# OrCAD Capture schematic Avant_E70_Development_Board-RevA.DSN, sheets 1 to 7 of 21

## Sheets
1 Title Page: title: Title Page; rev: 1.0; note: 305-PD-23-0976
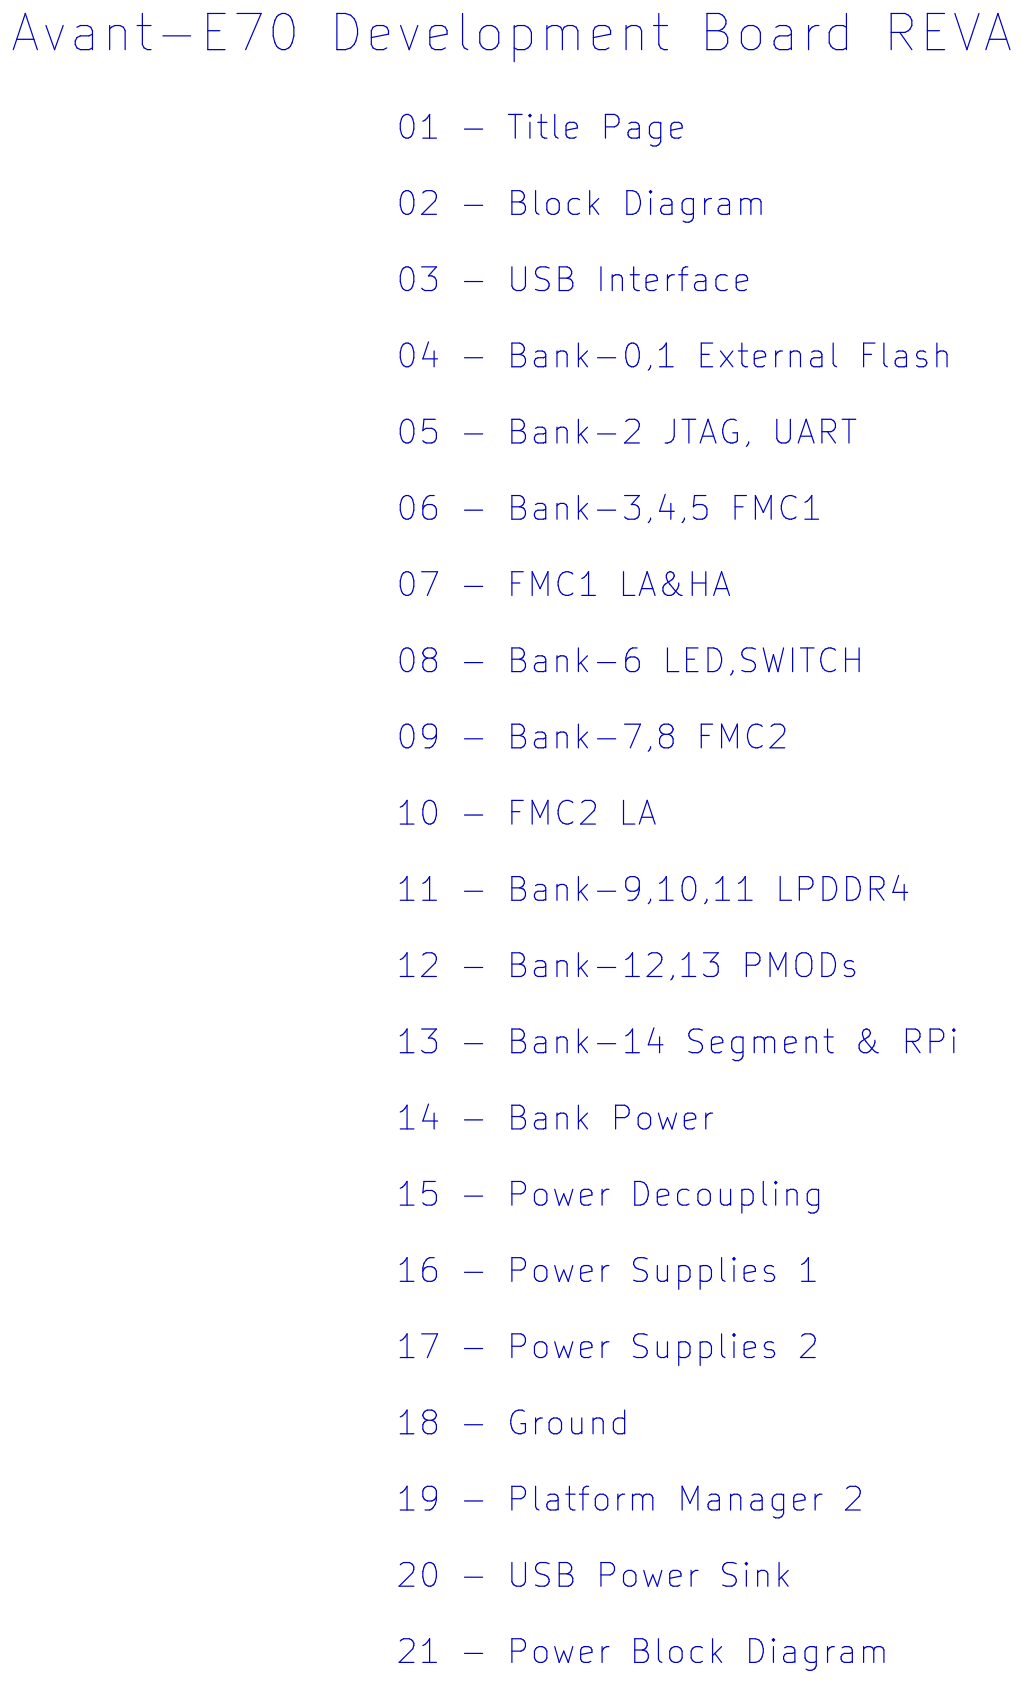
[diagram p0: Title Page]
2 Block Diagram: title: Block Diagram
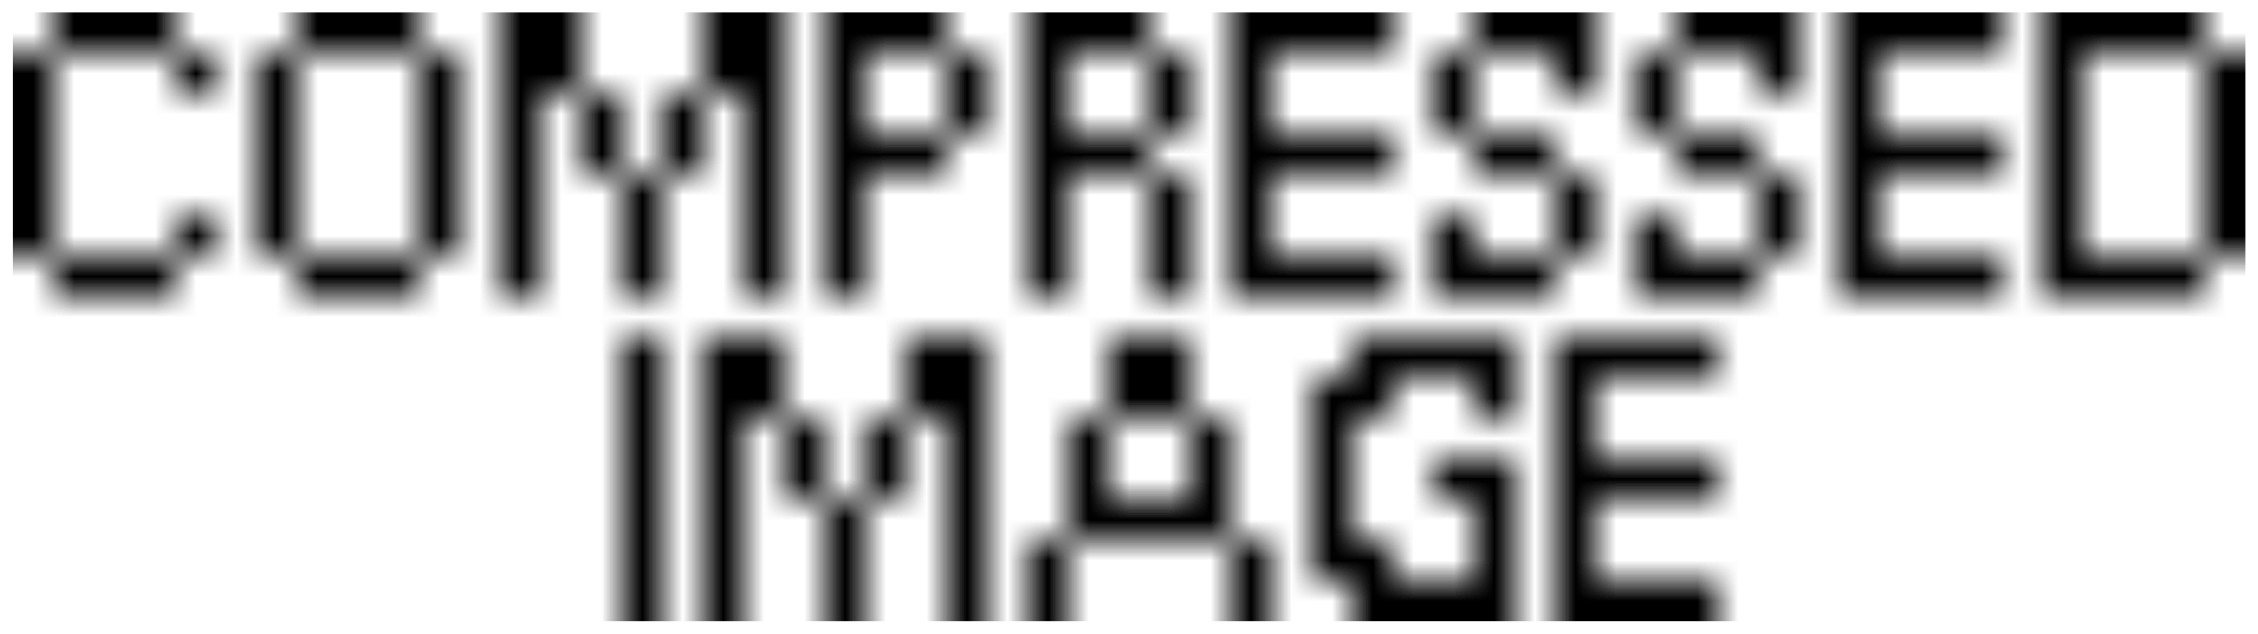
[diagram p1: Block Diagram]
3 USB Interface: size B; title: USB Interface
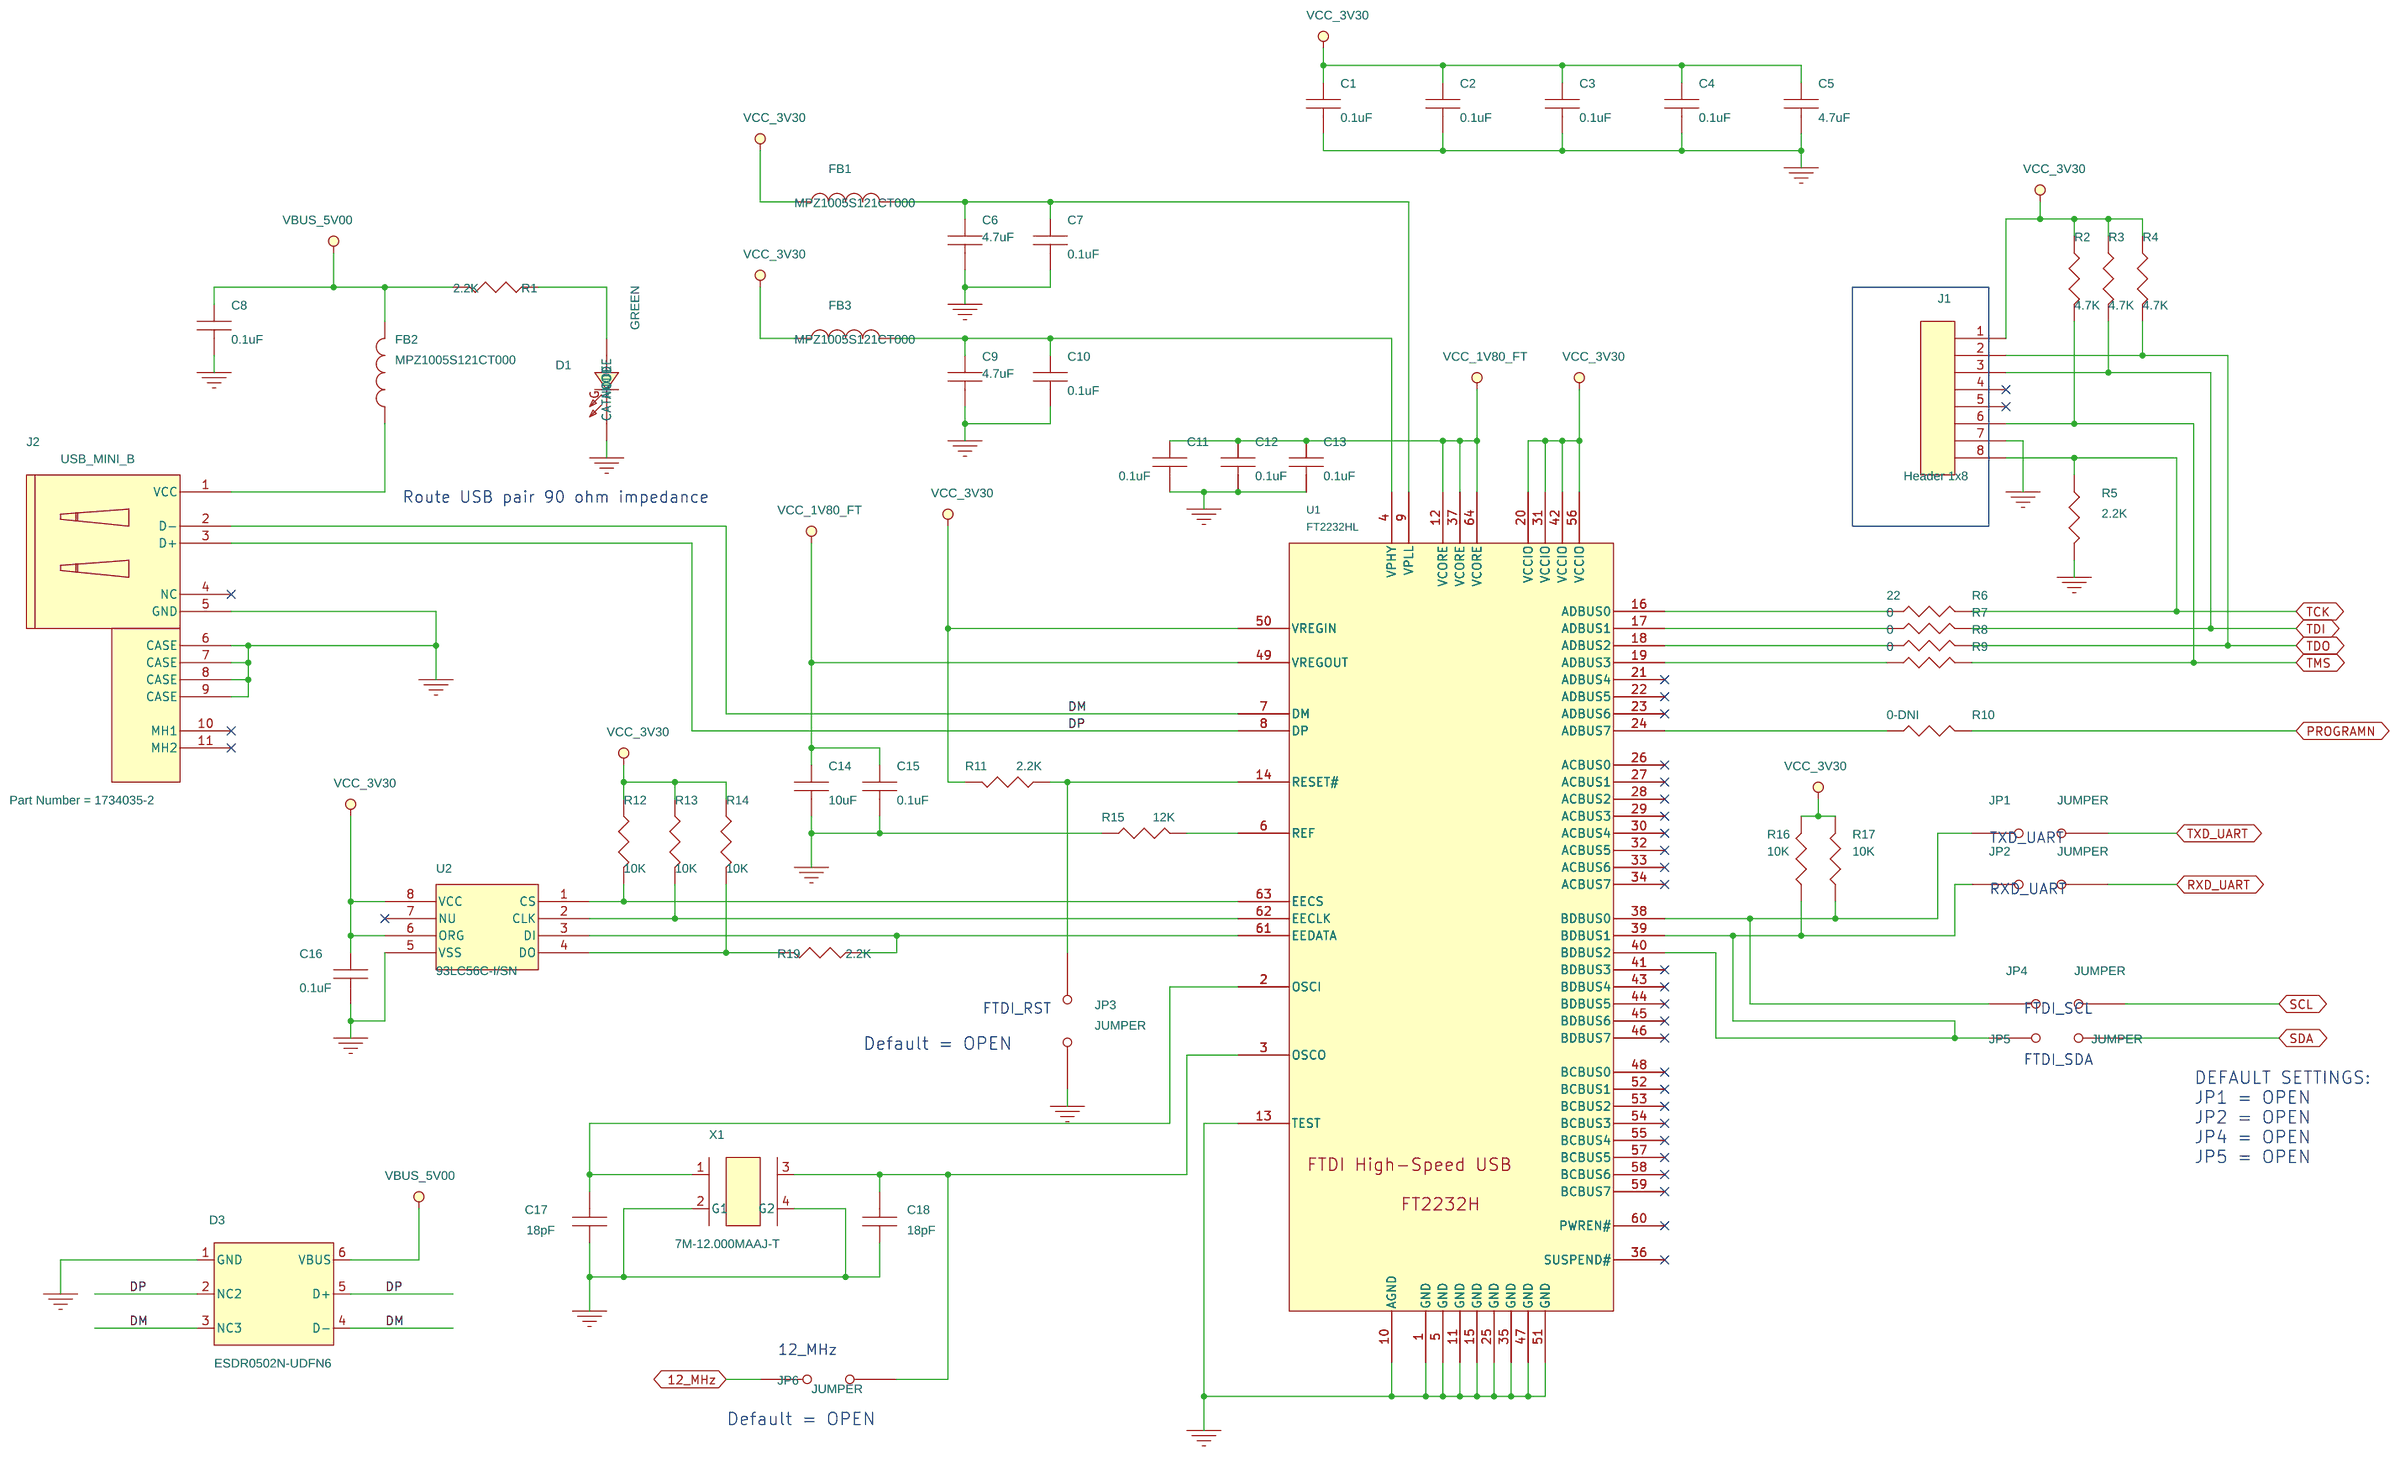
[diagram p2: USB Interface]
4 Bank-0,1 External Flash: size B; title: Bank-0,1 External Flash
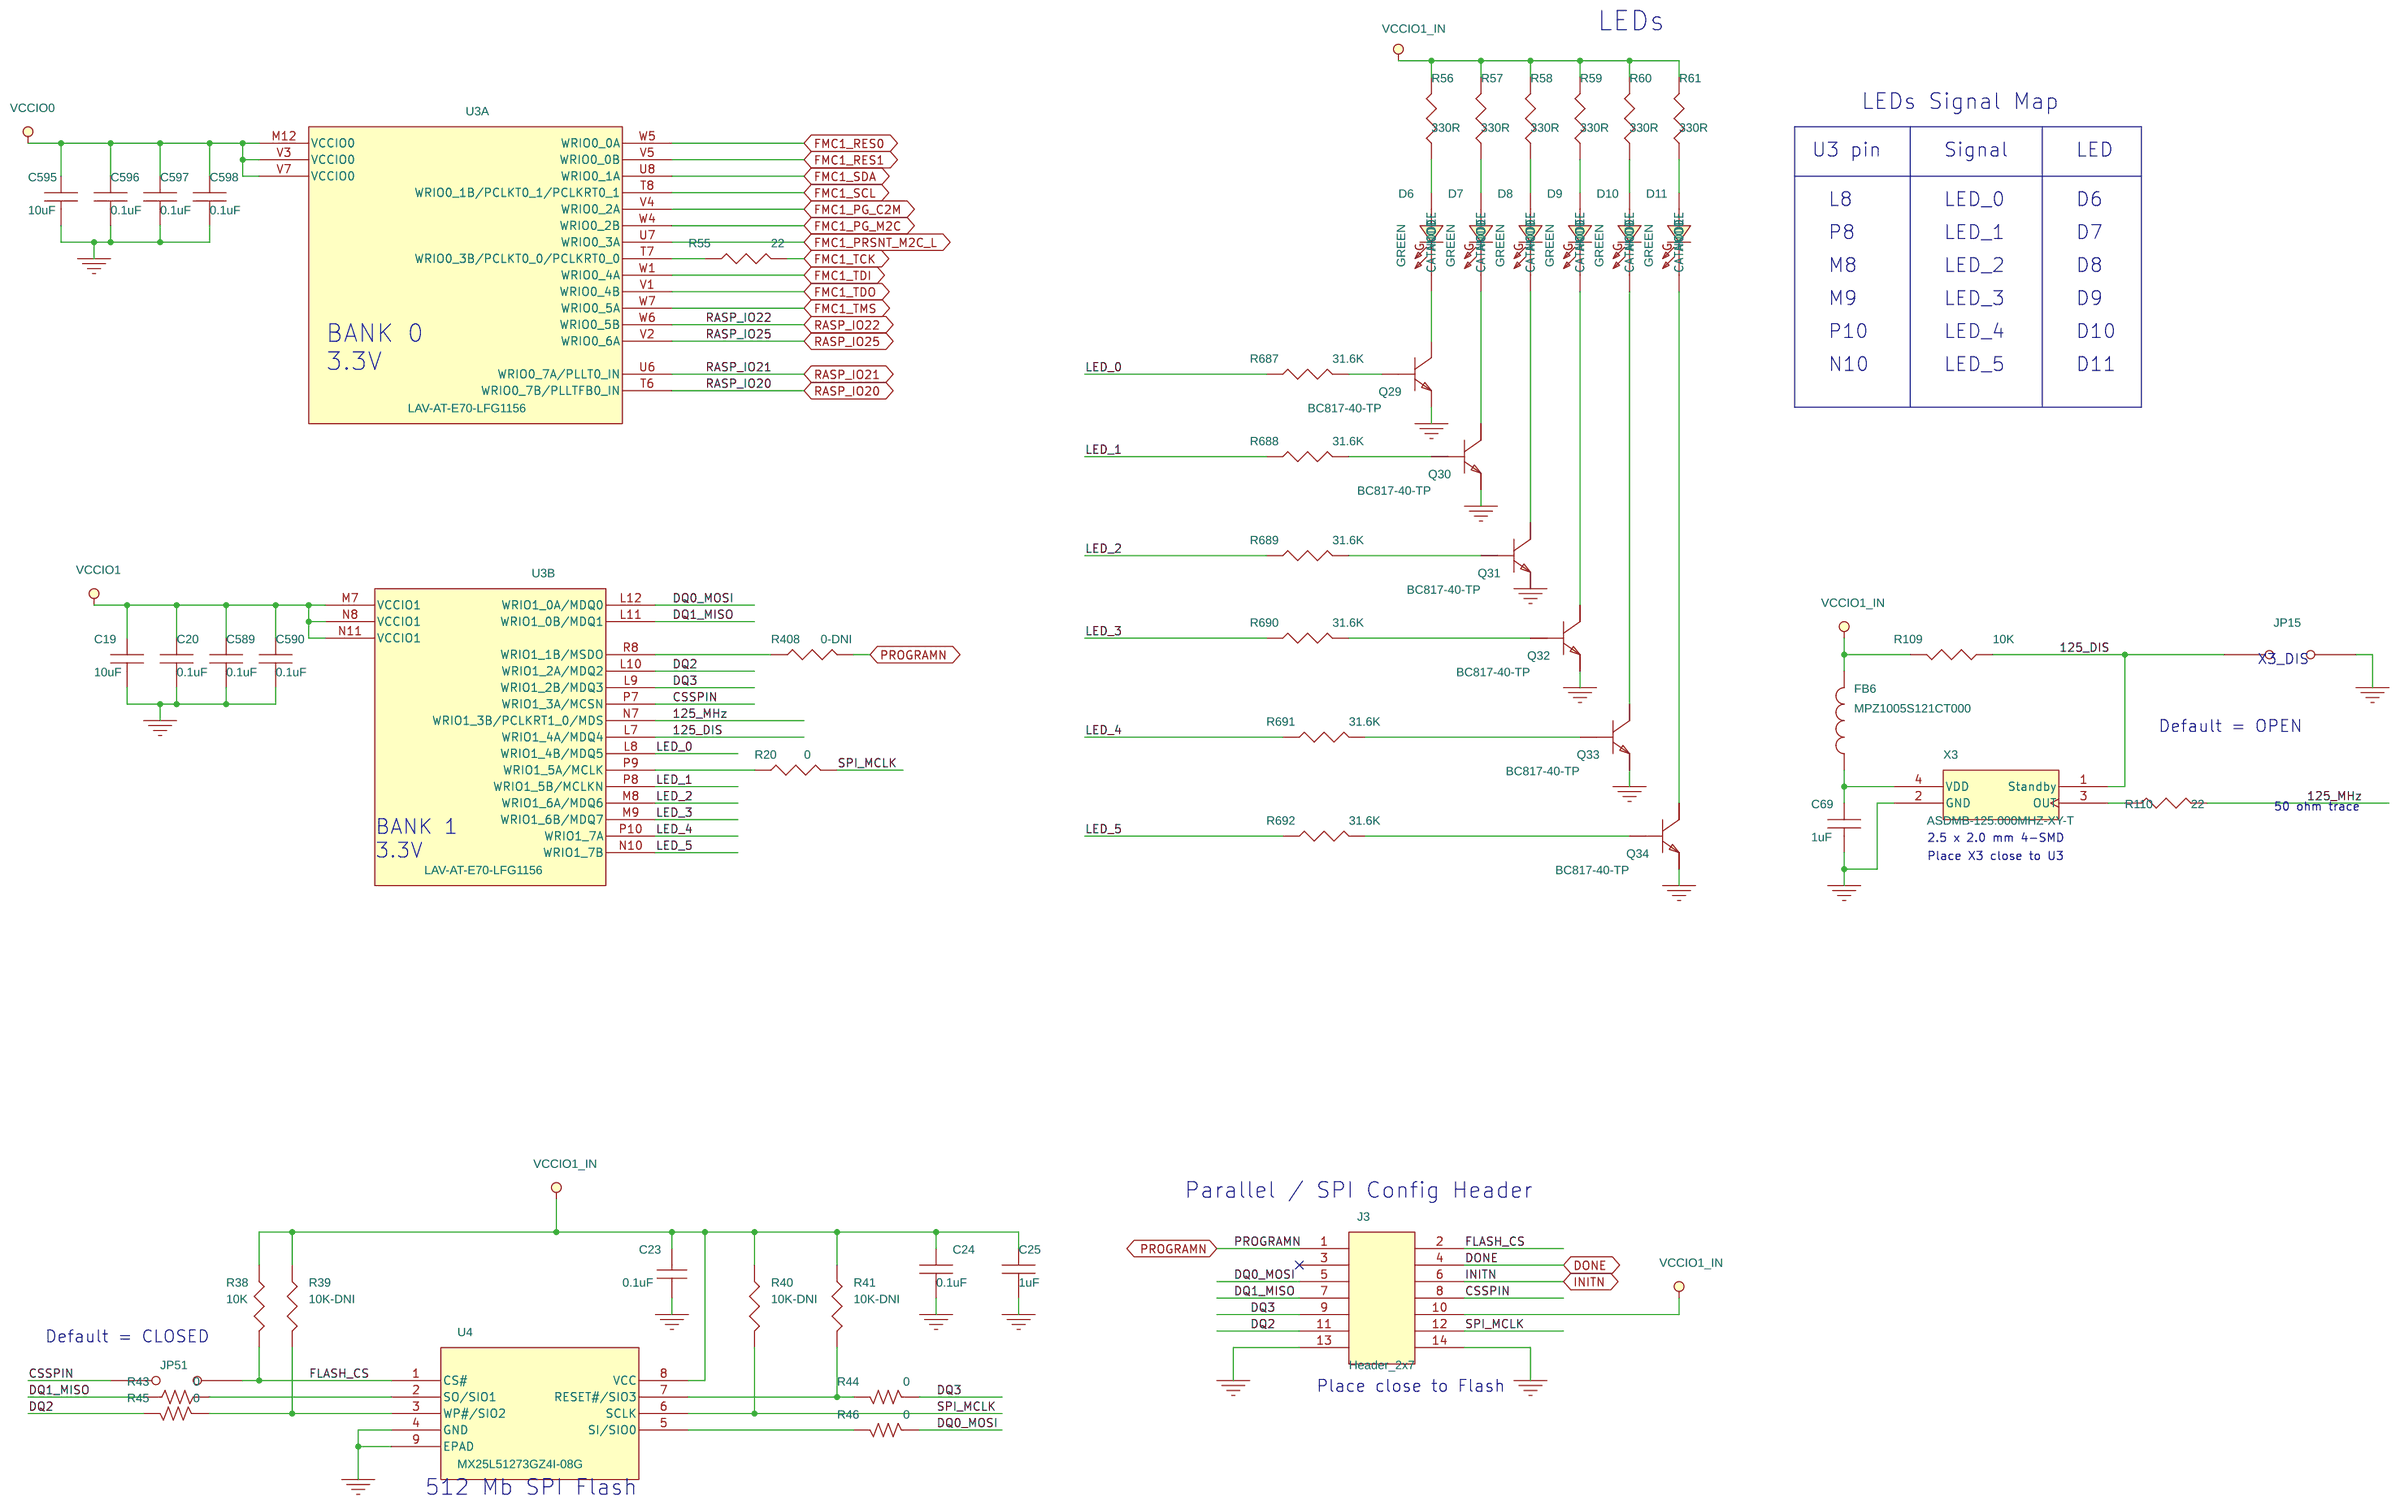
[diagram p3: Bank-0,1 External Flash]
5 Bank-2 JTAG, UART: size B; title: Bank-2 JTAG, UART
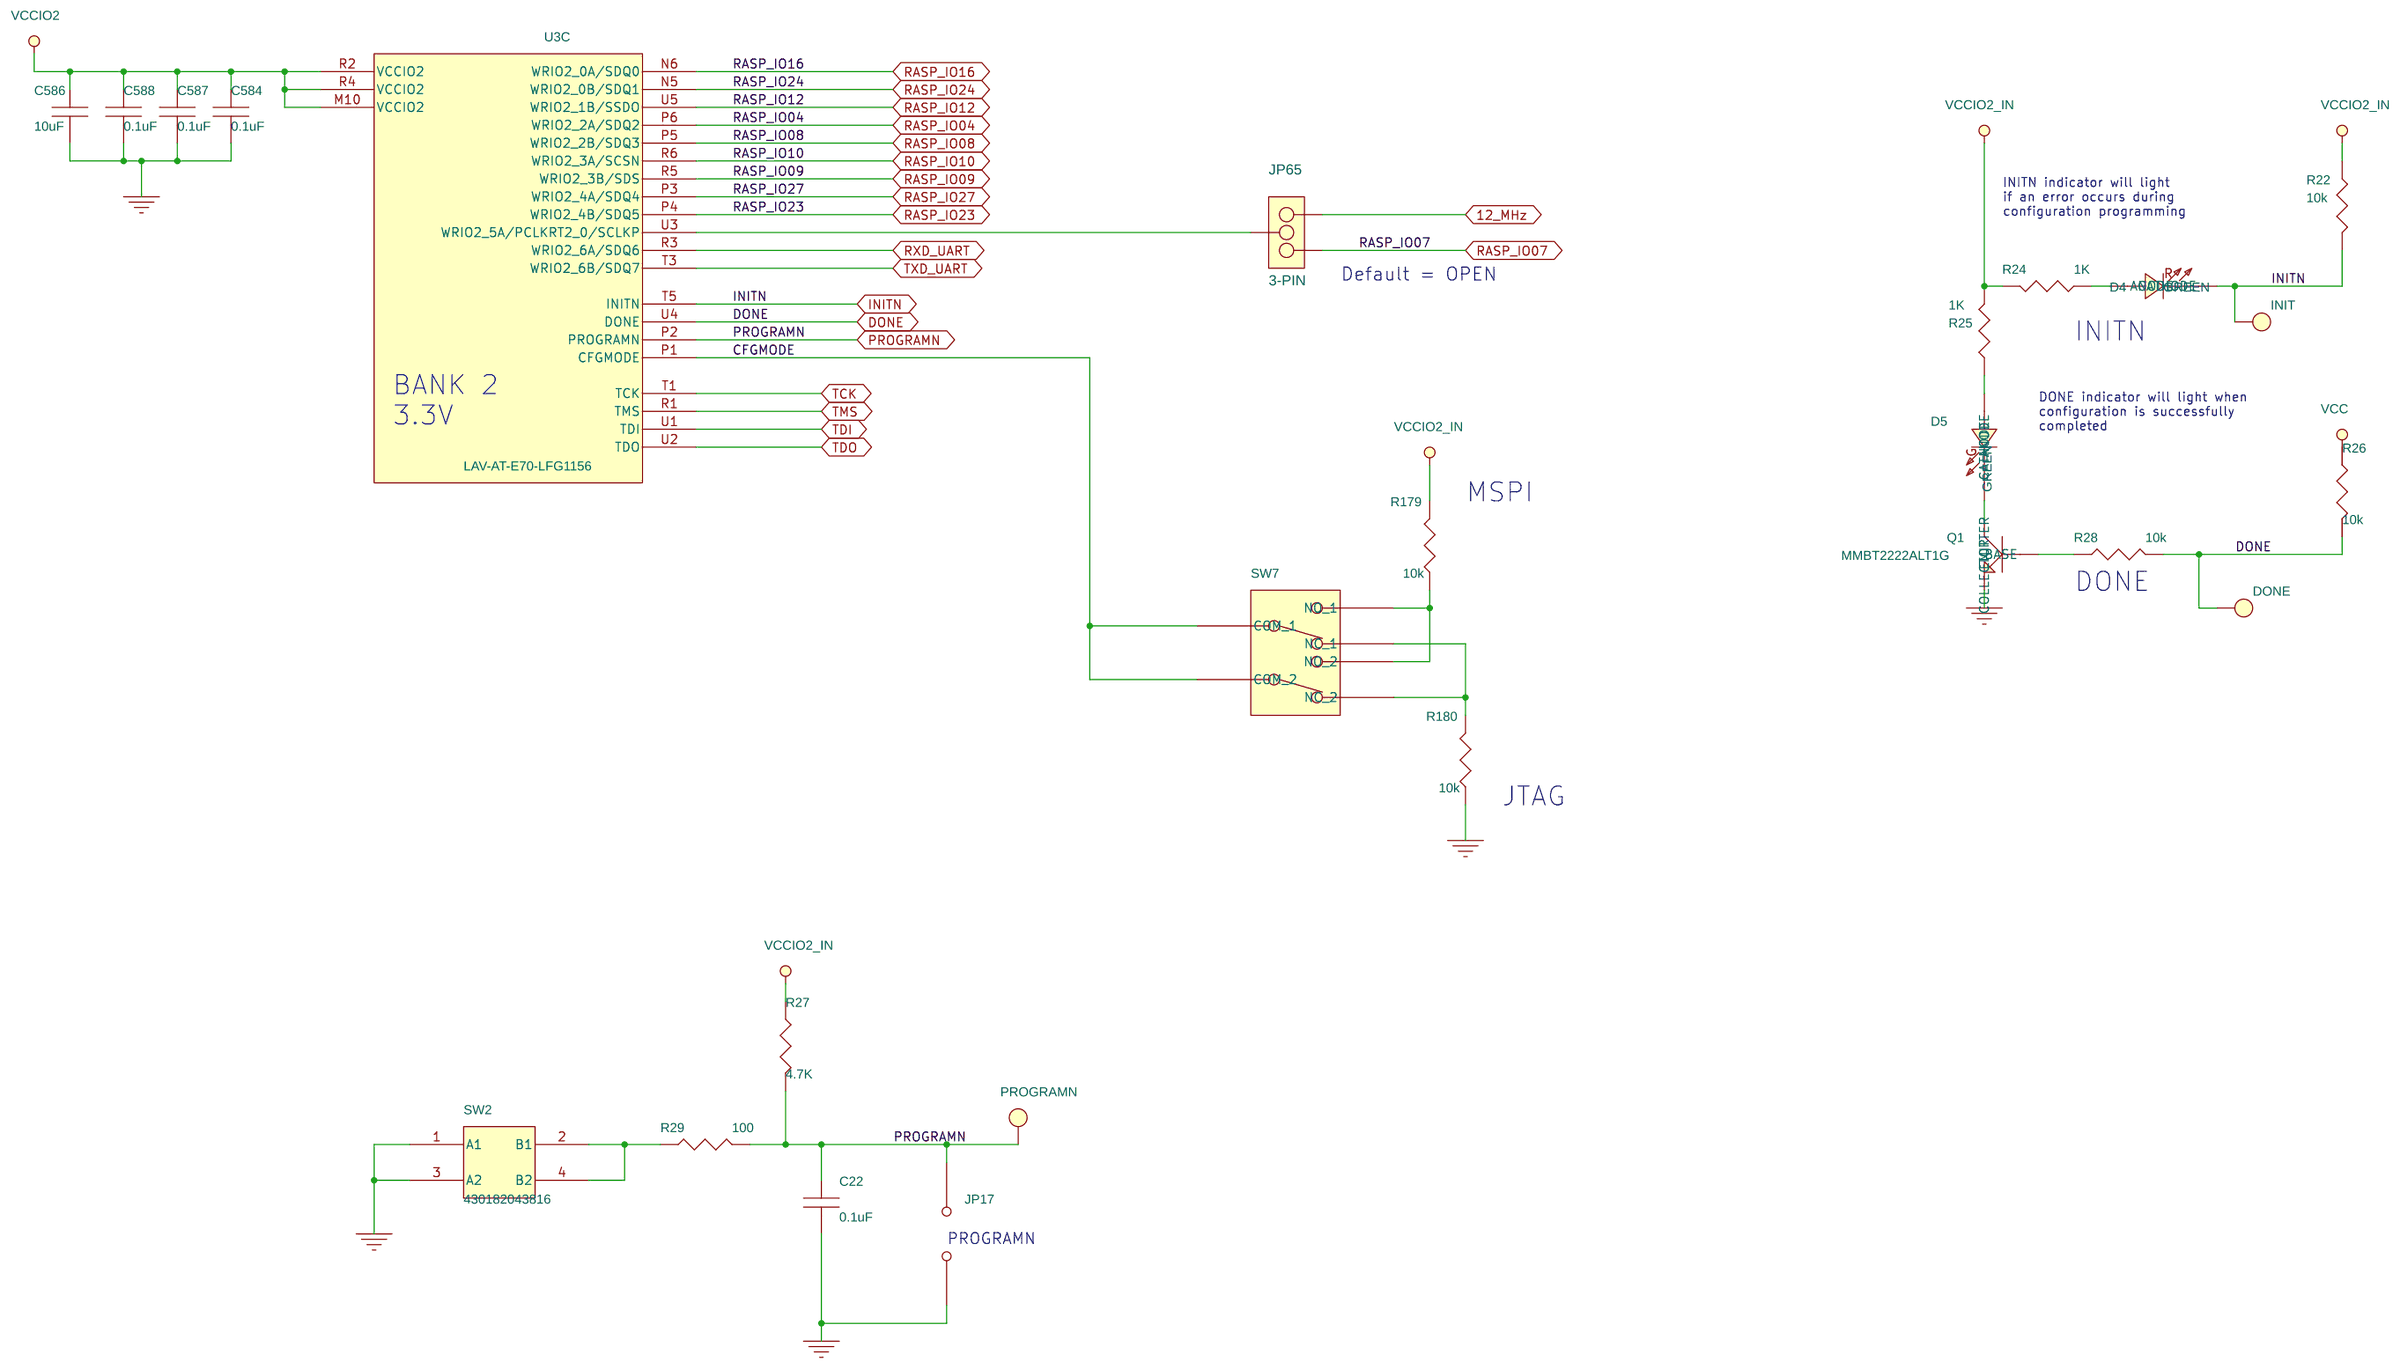
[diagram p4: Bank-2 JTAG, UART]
6 Bank-3,4,5 FMC1: size C; title: Bank-3,4,5 FMC1
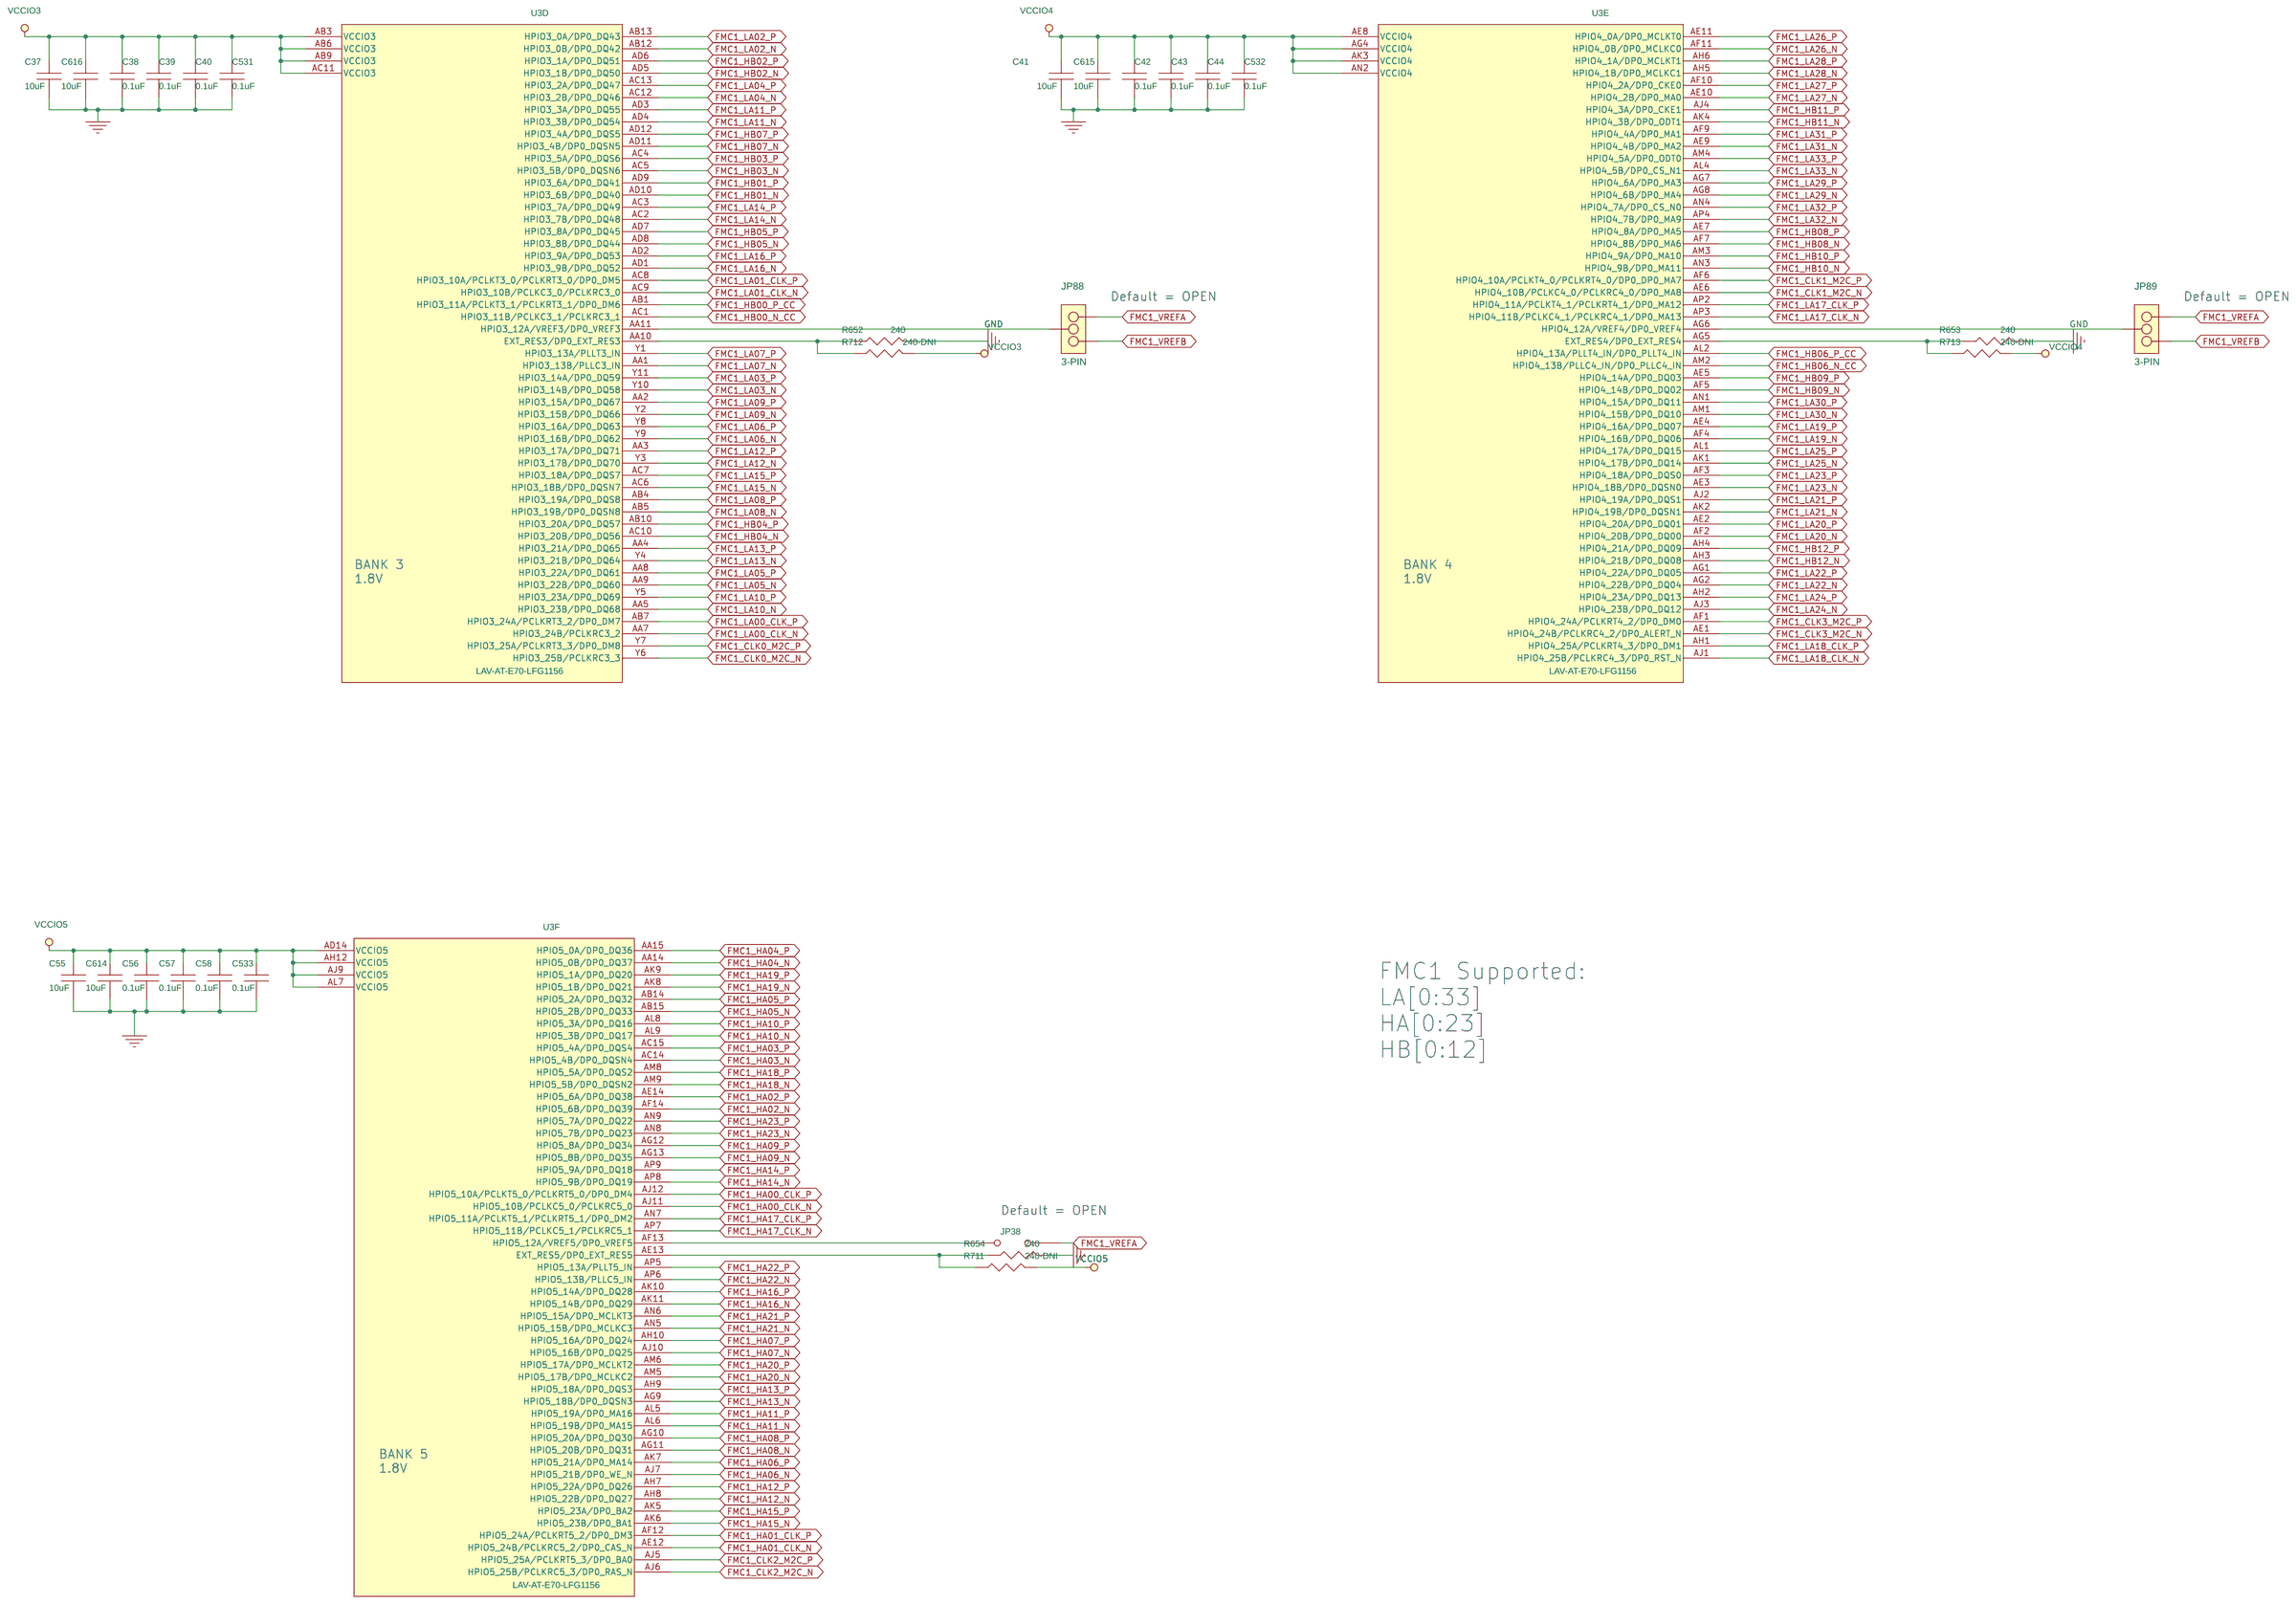
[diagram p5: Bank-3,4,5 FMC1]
7 FMC1 LA&HA: size C; title: FMC1 LA&HA
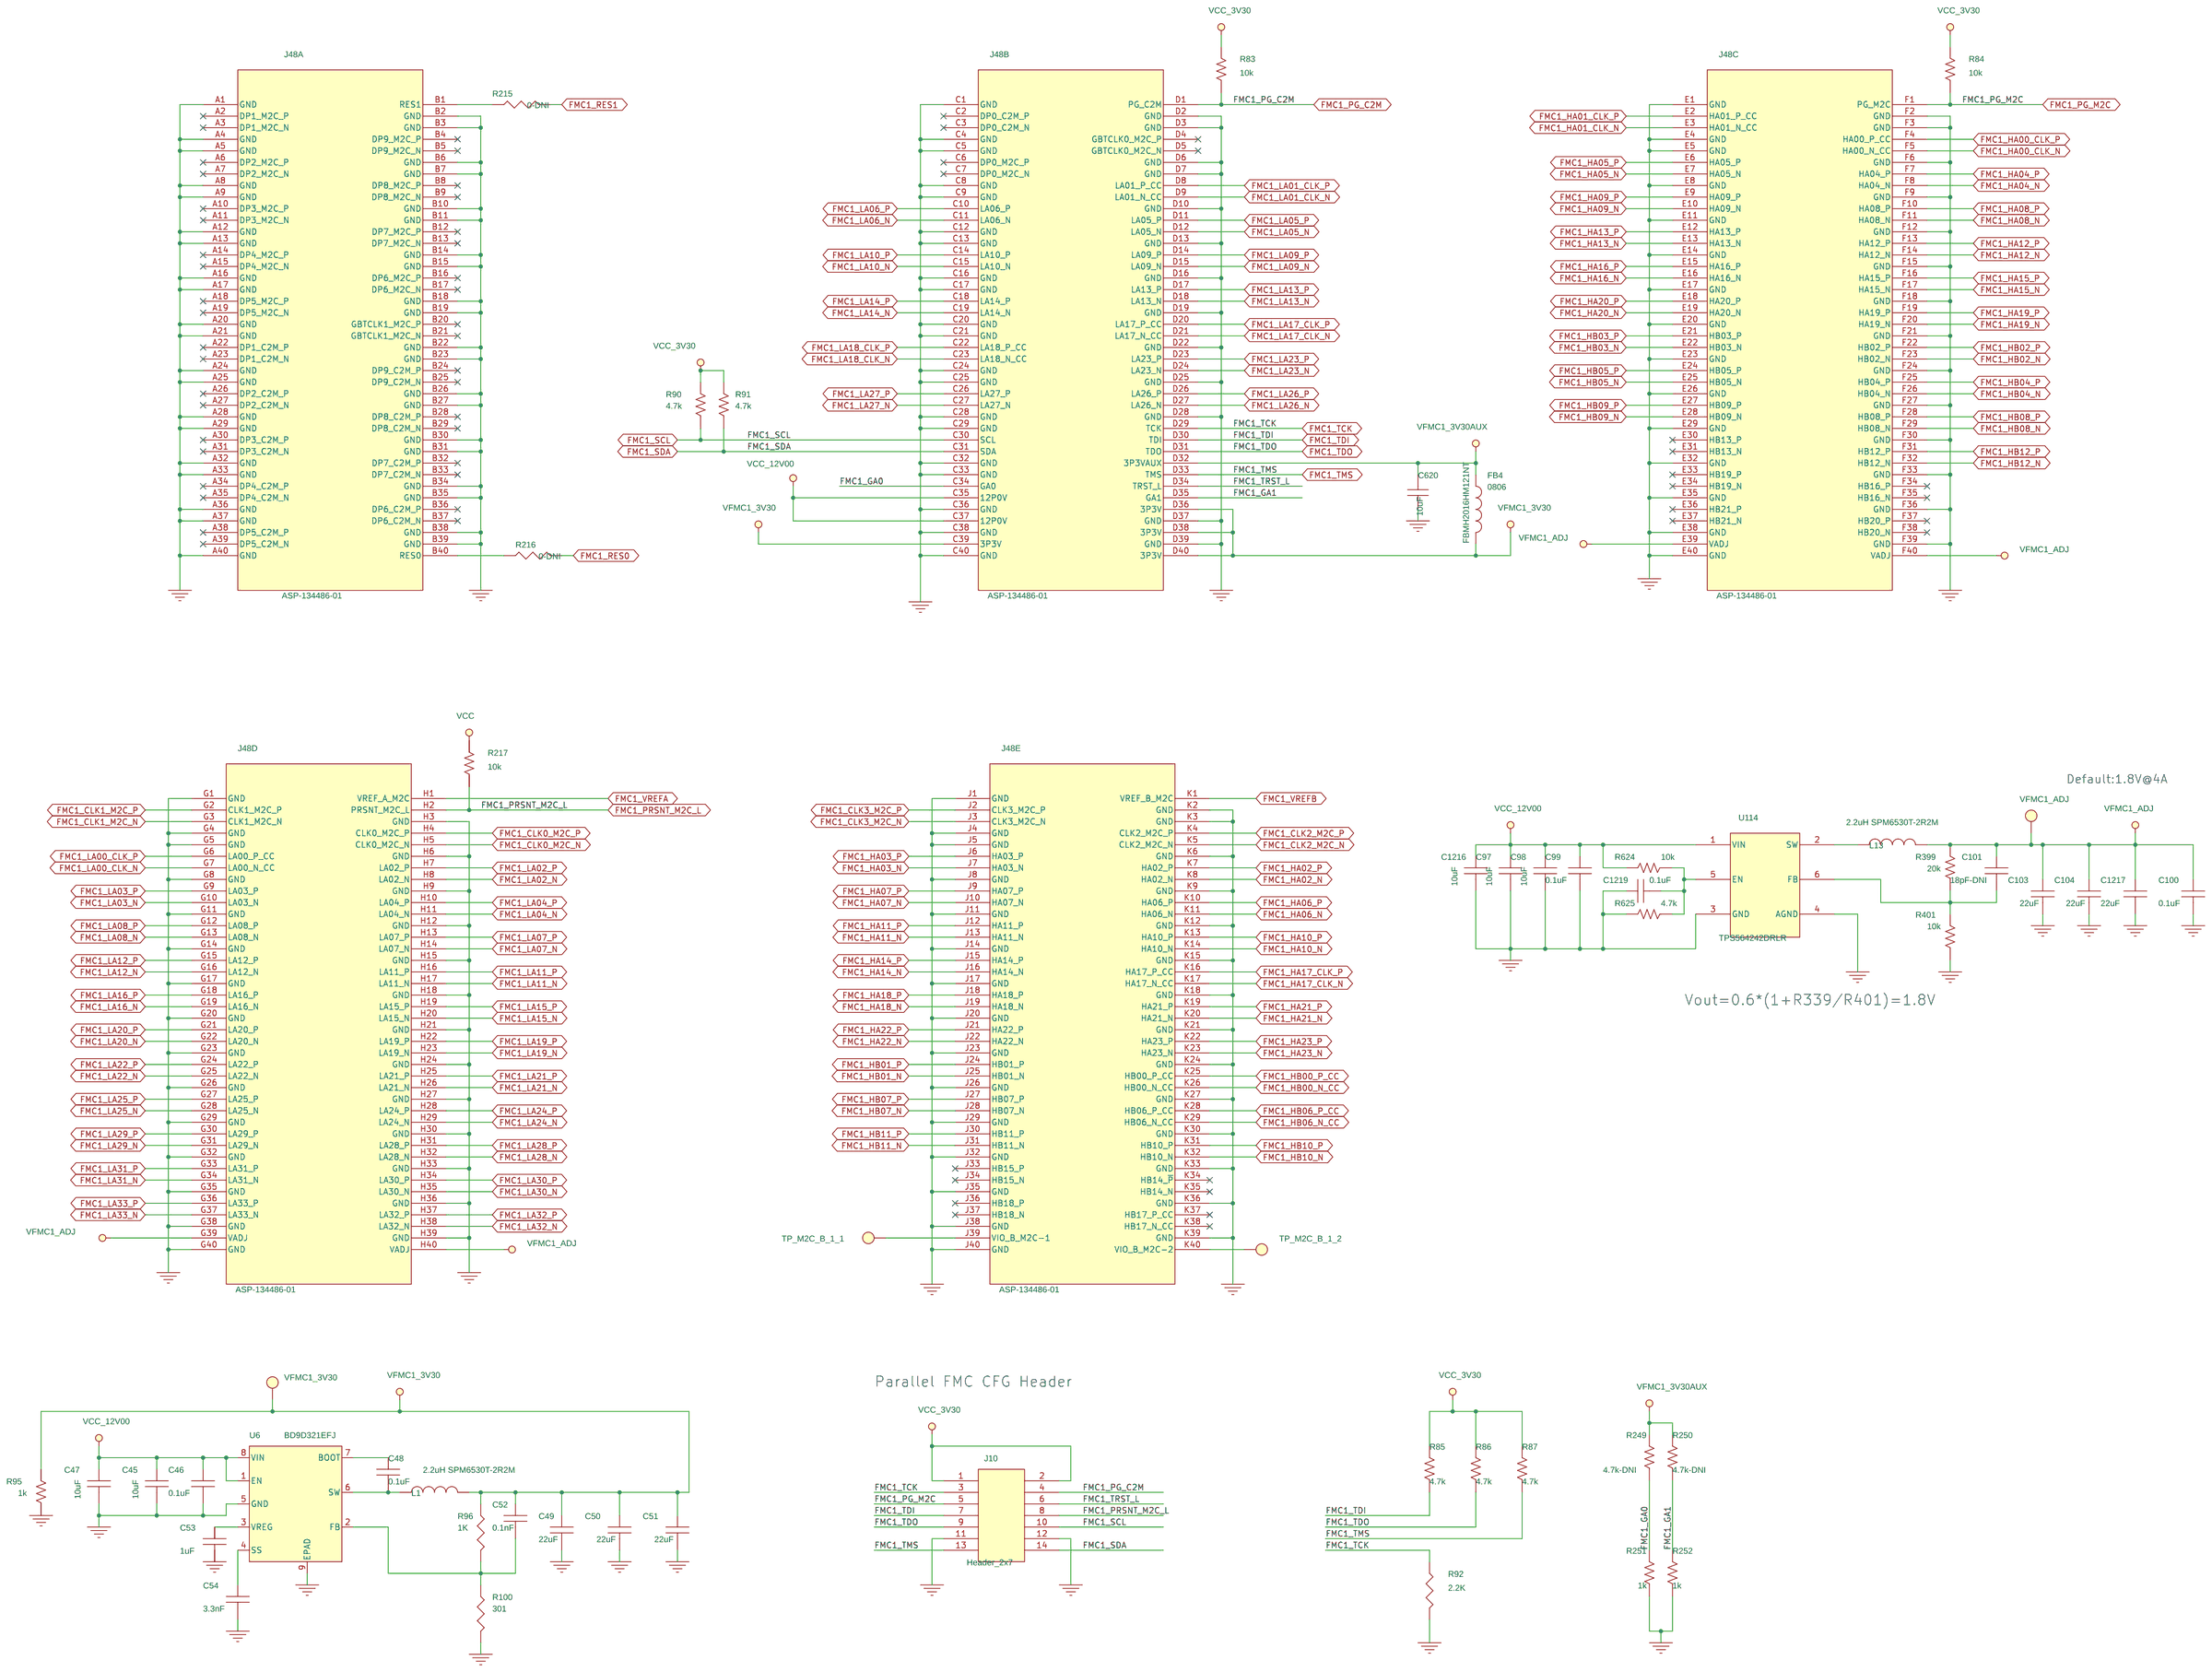
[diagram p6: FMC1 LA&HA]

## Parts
sheet Bank-0,1 External Flash
C19  10uF  [C0402]
C20  0.1uF  [C0201]
C23  0.1uF  [C0201]
C24  0.1uF  [C0201]
C25  1uF  [C0603]
C69  1uF  [C0603]
C589  0.1uF  [C0201]
C590  0.1uF  [C0201]
C595  10uF  [C0402]
C596  0.1uF  [C0201]
C597  0.1uF  [C0201]
C598  0.1uF  [C0201]
D6  GREEN  [APT1608]
D7  GREEN  [APT1608]
D8  GREEN  [APT1608]
D9  GREEN  [APT1608]
D10  GREEN  [APT1608]
D11  GREEN  [APT1608]
FB6  MPZ1005S121CT000  [FB0402]
J3  Header_2x7  [Header_2x7]
JP15  JUMPER  [Header_1x2]
JP51  J-2 Pin Jumper  [0p1_2-Pin_TH]
Q29  BC817-40-TP  [SOT23-3]
Q30  BC817-40-TP  [SOT23-3]
Q31  BC817-40-TP  [SOT23-3]
Q32  BC817-40-TP  [SOT23-3]
Q33  BC817-40-TP  [SOT23-3]
Q34  BC817-40-TP  [SOT23-3]
R20  0  [R0402]
R38  10K  [R0402]
R39  10K-DNI  [R0402]
R40  10K-DNI  [R0402]
R41  10K-DNI  [R0402]
R43  0  [R0402]
R44  0  [R0402]
R45  0  [R0402]
R46  0  [R0402]
R55  22  [R0402]
R56  330R  [R0603]
R57  330R  [R0603]
R58  330R  [R0603]
R59  330R  [R0603]
R60  330R  [R0603]
R61  330R  [R0603]
R109  10K  [R0603]
R110  22  [R0402]
R408  0-DNI  [R0402]
R687  31.6K  [R0603]
R688  31.6K  [R0603]
R689  31.6K  [R0603]
R690  31.6K  [R0603]
R691  31.6K  [R0603]
R692  31.6K  [R0603]
U4  MX25L51273GZ4I-08G  [8-WSON]
X3  ASDMB-125.000MHZ-XY-T  [x4-2520]
sheet Bank-2 JTAG, UART
C22  0.1uF  [C0201]
C584  0.1uF  [C0201]
C586  10uF  [C0402]
C587  0.1uF  [C0201]
C588  0.1uF  [C0201]
D4  GREEN  [APT1608]
D5  GREEN  [APT1608]
DONE  TestPoint  [TP50]
INIT  TestPoint  [TP50]
JP17  JUMPER  [Header_1x2]
JP65  3-PIN  [HDR254M-1X3]
PROGRAMN  TestPoint_SMT  [TPC32]
Q1  MMBT2222ALT1G  [MMBT2222ALT-1]
R22  10k  [R0603]
R24  1K  [R0603]
R25  1K  [R0603]
R26  10k  [R0603]
R27  4.7K  [R0603]
R28  10k  [R0603]
R29  100  [R0402]
R179  10k  [R0402]
R180  10k  [R0402]
SW2  430182043816  [430182043816]
SW7  SW-Wurth_452403012014  [452403012014]
sheet Bank-3,4,5 FMC1
C37  10uF  [C0402]
C38  0.1uF  [C0201]
C39  0.1uF  [C0201]
C40  0.1uF  [C0201]
C41  10uF  [C0402]
C42  0.1uF  [C0201]
C43  0.1uF  [C0201]
C44  0.1uF  [C0201]
C55  10uF  [C0402]
C56  0.1uF  [C0201]
C57  0.1uF  [C0201]
C58  0.1uF  [C0201]
C531  0.1uF  [C0201]
C532  0.1uF  [C0201]
C533  0.1uF  [C0201]
C614  10uF  [C0402]
C615  10uF  [C0402]
C616  10uF  [C0402]
JP38  J-2 Pin Jumper  [0p1_2-Pin_TH]
JP88  3-PIN  [HDR254M-1X3]
JP89  3-PIN  [HDR254M-1X3]
R652  240  [R0402]
R653  240  [R0402]
R654  240  [R0402]
R711  240-DNI  [R0402]
R712  240-DNI  [R0402]
R713  240-DNI  [R0402]
sheet Bank-12,13 PMODs
U3  LAV-AT-E70-LFG1156  [LAV-AT-500-L_1156]  (sections A,B,C,D,E,F,G,H,I,J,K,L,M,N,O,P,Q,R,S,T,U)
sheet FMC1 LA&HA
C45  10uF  [C0603]
C46  0.1uF  [C0201]
C47  10uF  [C0603]
C48  0.1uF  [C0201]
C49  22uF  [C0603]
C50  22uF  [C0603]
C51  22uF  [C0603]
C52  0.1nF  [C0603]
C53  1uF  [C0603]
C54  3.3nF  [C0201]
C97  10uF  [C0603]
C98  10uF  [C0603]
C99  0.1uF  [C0201]
C100  0.1uF  [C0201]
C101  18pF-DNI  [C0402]
C103  22uF  [C0603]
C104  22uF  [C0603]
C620  10uF  [C0402]
C1216  10uF  [C0603]
C1217  22uF  [C0603]
C1219  0.1uF  [C0201]
FB4  FBMH2016HM121NT  [0806]
J10  Header_2x7  [Header_2x7]
J48  ASP-134486-01  [ASP-134486-01]  (sections A,B,C,D,E)
L1  2.2uH SPM6530T-2R2M  [SPM6530T-2R2M]
L13  2.2uH SPM6530T-2R2M  [SPM6530T-2R2M]
R83  10k  [R0603]
R84  10k  [R0603]
R85  4.7k  [R0603]
R86  4.7k  [R0603]
R87  4.7k  [R0603]
R90  4.7k  [R0603]
R91  4.7k  [R0603]
R92  2.2K  [R0603]
R95  1k  [R0603]
R96  1K  [R0402]
R100  301  [R0402]
R215  0-DNI  [R0603]
R216  0-DNI  [R0603]
R217  10k  [R0603]
R249  4.7k-DNI  [R0603]
R250  4.7k-DNI  [R0603]
R251  1k  [R0603]
R252  1k  [R0603]
R399  20k  [R0603]
R401  10k  [R0603]
R624  10k  [R0603]
R625  4.7k  [R0603]
TP_M2C_B_1_1  TestPoint  [TP50]
TP_M2C_B_1_2  TestPoint  [TP50]
U6  BD9D321EFJ  [HTSOP_8_BD9D321]
U114  TPS564242DRLR  [SOT-563-6]
VFMC1_3V30  VTTVREF  [TP_50]
VFMC1_ADJ  TestPoint_SMT  [TPC32]
sheet USB Interface
C1  0.1uF  [C0201]
C2  0.1uF  [C0201]
C3  0.1uF  [C0201]
C4  0.1uF  [C0201]
C5  4.7uF  [C0603]
C6  4.7uF  [C0603]
C7  0.1uF  [C0201]
C8  0.1uF  [C0201]
C9  4.7uF  [C0603]
C10  0.1uF  [C0201]
C11  0.1uF  [C0201]
C12  0.1uF  [C0201]
C13  0.1uF  [C0201]
C14  10uF  [C0402]
C15  0.1uF  [C0201]
C16  0.1uF  [C0201]
C17  18pF  [C0402]
C18  18pF  [C0402]
D1  GREEN  [APT1608]
D3  ESDR0502N-UDFN6  [UDFN6_040]
FB1  MPZ1005S121CT000  [FB0402]
FB2  MPZ1005S121CT000  [FB0402]
FB3  MPZ1005S121CT000  [FB0402]
J1  Header 1x8  [hdr_amp_87220_8_1x8_100]
J2  USB_MINI_B  [USB_MINI_B-1734035-2]
JP1  JUMPER  [Header_1x2]
JP2  JUMPER  [Header_1x2]
JP3  JUMPER  [Header_1x2]
JP4  JUMPER  [Header_1x2]
JP5  JUMPER  [Header_1x2]
JP6  JUMPER  [Header_1x2]
R1  2.2K  [R0603]
R2  4.7K  [R0603]
R3  4.7K  [R0603]
R4  4.7K  [R0603]
R5  2.2K  [R0603]
R6  22  [R0402]
R7  0  [R0402]
R8  0  [R0402]
R9  0  [R0402]
R10  0-DNI  [R0402]
R11  2.2K  [R0603]
R12  10K  [R0603]
R13  10K  [R0603]
R14  10K  [R0603]
R15  12K  [R0603]
R16  10K  [R0603]
R17  10K  [R0603]
R19  2.2K  [R0603]
U1  FT2232HL  [tqfp64_0p5_12p2x12p2_h1p6]
U2  93LC56C-I/SN  [so8_50_244]
X1  7M-12.000MAAJ-T  [xtal_4p_7m]

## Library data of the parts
C19 C37 C41 C55 C586 C595 C614-C616 = 10uF_0603
C1-C5 C7 C8 C10-C13 C16 C20 C24 C25 C38-C40 C42-C44 C46 C48 C56-C58 C99 C100 C531-C533 C584 C587-C590 C596-C598 C1219 = 0u1_0402: CAP CER 0.1UF 25V 10% X5R 0201; Manufacturer: Murata; Manufacturer Part Number: GRM033R61E104KE14J
C23 C620 = CAP_NP: COMPFIXED: NO; COMPGROUP: 0; COMPHEIGHT: 0.000; COMPKEY: NO; COMPLOC: [1820.000,2015.000]; COMPLOCKED: NO; COMPROT: 270; COMPSIDE: TOP; DECOUPLER: NO; FPLIST: SM/C_0402; MEMORY: NO
C15 C22 C69 = 0u1_0402: CAP CER 0.1UF 16V 10% X7R 0402
D1 D5-D11 = LED-SMT1206_GREEN_3
FB1-FB3 FB6 = INDUCTOR_1: FERRITE BEAD 120 OHM 0402 1LN; Manufacturer: TDK Corporation
J3 J10 = Header_2x7
JP1-JP6 JP15 JP17 = JUMPER_0
JP38 JP51 = J-2_Pin_Jumper: Manufacturer Part Number: 22-28-4020
Q29-Q34 = TRANS_NPN_45V_0_0.8A_SOT-23: TRANS NPN 45V 0.8A SOT-23; Manufacturer: Micro Commercial Co
R20 R55 R408 = R_v2: RES SMD 33 OHM 1% 1/10W 0402; Manufacturer: Panasonic; Manufacturer Part Number: ERJ-2RKF33R0X
R38 = R0402_10K_5%_VISHAY: Manufacturer Part Number: CRCW040210K0JNED
R39-R41 = R0402_10K_NP: Manufacturer Part Number: ERJ-2GEJ103X
R43-R46 = R: RES SMD 0.0OHM JUMPER 1/10W 0402; COMPFIXED: NO; COMPHEIGHT: 0.000; COMPKEY: NO; COMPLOC: [3325.000,1400.000]; COMPLOCKED: NO; COMPROT: 180; COMPSIDE: TOP; DECOUPLER: NO; FPLIST: AX/RC05; MEMORY: NO; Manufacturer: Panasonic; Manufacturer Part Number: ERJ-2GE0R00X
R24 R25 R56-R61 = 1k_0402: RES 1K OHM 1/10W 1% 0603 SMD; Digikey P/N: 311-1.00KHRCT-ND; Manufacturer Part Number: RC0603FR-071KL
R109 = RESISTOR: RES 10K OHM 1/10W 5% 0603
R110 = 1R_0.25W_0603: Manufacturer: Vishay
R687-R692 = R_10K_0603: Manufacturer Part Number: RC1608F103CS
U4 = U-W25Q512JVEIM_512Mb_Flash_0
X3 = ASDMB: Assy: DNI
D4 = LED-SMT1206_RED_2
DONE INIT TP_M2C_B_1_1 TP_M2C_B_1_2 = T_POINT_R
JP65 JP88 JP89 = 3-PINS_0.1_SINGLE_LINE_PIN
PROGRAMN VFMC1_ADJ = T_POINT_R: Assy: DNI
Q1 = 2N2222_0
R22 R26 = R_v2: RES SMD 10K OHM 1% 1/16W 0402; MFG: Yageo; MFG P/N: RC0402FR-0710KL; Manufacturer: Yageo; Manufacturer Part Number: RC0402FR-0710KL
R2-R4 R27 = 5k1_0402: RES 4.70K OHM 1/10W 1% 0603 SMD; Digikey P/N: 541-4.70KHTR-ND; Manufacturer: Vishay; Manufacturer Part Number: CRCW06034K70FKEA
R28 = RES_0: RES SMD 10K OHM 1% 1/16W 0402; MFG: Yageo; MFG P/N: RC0402FR-0710KL; Manufacturer: Yageo; Manufacturer Part Number: RC0402FR-0710KL
R29 = RES_10K_1W16_0402_5P: RES SMD 100 OHM 1% 1/10W 0402; Digikey P/N: RMCF0603JT10K0TR-ND; MFG: Pansonic; MFG P/N: ERJ-2RKF1000X; Manufacturer: Pansonic; Manufacturer Part Number: ERJ-2RKF1000X; Wattage: 1/10W
R179 R180 = RES_10K_1W16_0402_5P: RES SMD 10K OHM 1% 1/16W 0402; Digikey P/N: 311-10.0KLRTR-ND; Manufacturer: Yageo; Manufacturer Part Number: RC0402FR-0710KL
SW2 = EVQP0_0: SWITCH TACTILE SPST-NO 0.05A 12V; Cost Ea/1k: $ 0.11025 (1000-4999), 0.09135 (5000+); Digikey P/N: CKN9112TR-ND; Distributor: Digi-Key; MFG: C&K Components; Manufacturer: C&K Components
SW7 = SW-Wurth_452403012014
R7-R9 R652-R654 R711-R713 = 0R_0603: RES 0.0 OHM 1/10W JUMP 0603 SMD
U3 = LAV-AT-E70-LFG1156_6
C45 C47 C97 C98 C1216 = 10uF_0603: CAP CER 10UF 25V X5R 1206; Manufacturer Part Number: TMK316BJ106KL-T
C49-C51 C103 C104 = 10uF_0603: CAP CER 22UF 10V X5R 0603; Manufacturer: Murata; Manufacturer Part Number: GRM188R61A226ME15D
C52 C101 = 10uF_0603: CAP CER 100PF 50V C0G/NPO 0603; Manufacturer: Yageo; Manufacturer Part Number: CC0603JRNPO9BN101
C53 C1217 = 10uF_0603: CAP CER 1UF 25V 10% X7R 0603; Manufacturer Part Number: TMK107B7105KA-T
C54 = 0u1_0402: CAP CER 3300PF 25V X7R 0201; Manufacturer: Murata; Manufacturer Part Number: GRM033R71E332KA12D
FB4 = FB_0806_120R_TaiyoYuden
J48 = ASP-134486-01_0
L1 L13 = INDUCTOR_0
R83-R87 R91 R95 R217 R249-R252 R399 R401 R624 R625 = R: RES SMD 4.7K OHM 5% 1/10W 0402; COMPFIXED: NO; COMPGROUP: 0; COMPHEIGHT: 0.000; COMPKEY: NO; COMPLOC: [970.000,1160.000]; COMPLOCKED: NO; COMPROT: 180; COMPSIDE: TOP; DECOUPLER: NO; FPLIST: AX/RC05,SM/R_0603; MEMORY: NO; MFG: Panasonic; MFG P/N: ERJ-2GEJ472X; Manufacturer: Panasonic; Manufacturer Part Number: ERJ-2GEJ472X
R90 = R: RES SMD 1K OHM 1% 1/10W 0402; COMPFIXED: NO; COMPGROUP: 0; COMPHEIGHT: 0.000; COMPKEY: NO; COMPLOC: [970.000,1160.000]; COMPLOCKED: NO; COMPROT: 180; COMPSIDE: TOP; DECOUPLER: NO; FPLIST: AX/RC05,SM/R_0603; MEMORY: NO; Manufacturer: Panasonic; Manufacturer Part Number: ERJ-2RKF1001X
R5 R11 R92 R215 R216 = 5k1_0402: Digikey P/N: 541-2.20KHTR-ND; Manufacturer: Vishay; Manufacturer Part Number: CRCW06032K20FKEA
R96 = R0402_1K_1%_Yageo: Manufacturer Part Number: RC0402FR-071KL
R100 = R0402_301R_1%_Yageo: Manufacturer Part Number: RC0402FR-07301RL
U6 = BD9D321EFJ
U114 = TPS564242DRLR
VFMC1_3V30 = TP_SMD
C6 C9 = 4u7_0603: CAP CER 4.7UF 6.3V 10% X5R 0603; Digikey P/N: PCC2396CT-ND
C14 = 10uF_0603: CAP CER 10UF 10V 20% X5R 0603
C17 C18 = 0u1_0402: CAP CER 18PF 25V 10% NP0 0402; Digikey P/N: C0402C180K3GACTU-ND; Manufacturer Part Number: C0402C180K3GACTU
D3 = ESDR0502: Manufacturer: Semtech; Manufacturer Part Number: RClamp0524P
J1 = header1x8_100: CONN HEADER 8POS .100 VERT TIN; Digikey P/N: WM50017-08-ND; Manufacturer Part Number: 22284081
J2 = USB_MINI_B_1: CONN RCPT USB2.0 MINI B SMD R/A; COMPFIXED: NO; COMPGROUP: 0; COMPHEIGHT: 0.000; COMPKEY: NO; COMPLOC: [370.000,2590.000]; COMPLOCKED: NO; COMPROT: 270; COMPSIDE: TOP; DECOUPLER: NO; FPLIST: TYPE_B; MEMORY: NO; Manufacturer: TE Connectivity AMP Connectors; Manufacturer Part Number: 1734035-2; Part Number: 1734035-2; Populate: <Populate>
R1 R15 R19 = 10k_0402: RES 12K OHM 1/10W 1% 0603 SMD; Digikey P/N: 311-12.0KHRTR-ND; Manufacturer Part Number: RC0603FR-0712KL; Tolerance: 1%
R6 = 0R_0603: RES SMD 33 OHM 1% 1/10W 0402; Manufacturer: Panasonic; Manufacturer Part Number: ERJ-2RKF33R0X
R10 = 0R_0603: RES SMD 1K OHM 1% 1/10W 0603; Assy: DNI; Manufacturer Part Number: RC0603FR-071KL
R12-R14 = RES_10K_1W16_0402_5P: RES 10K OHM 1/10W 5% 0603; Digikey P/N: RMCF0603JT10K0TR-ND; Manufacturer: Stackpole Electronics Inc; Manufacturer Part Number: RMCF0603JT10K0; Wattage: 1/10W
R16 R17 = RESISTOR: Populate: <Populate>
U1 = FT2232HL: IC USB HS DUAL UART/FIFO 64-LQFP; Assy: Customer Supplied
U2 = 93LC56_SO8_0: IC EEPROM 2KBIT 3MHZ 8SOIC
X1 = crystal-3p2x2p5: CRYSTAL 12MHZ 18PF SMD; Manufacturer: Suntsu Electronics, Inc.; Manufacturer Part Number: SXT32418BB16-12.000M

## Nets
GND: C1.2 C2.2 C3.2 C4.2 C5.2 C6.2 C7.2 C8.2 C9.2 C10.2 C11.2 C12.2 C13.2 C14.2 C15.2 C16.2 C17.1 C18.1 C19.2 C20.2 C22.2 C23.1 C24.2 C25.2 C37.2 C38.2 C39.2 C40.2 C41.2 C42.2 C43.2 C44.2 C45.2 C46.2 C47.2 C49.2 C50.2 C51.2 C53.2 C54.2 C55.2 C56.2 C57.2 C58.2 C69.2 C97.2 C98.2 C99.2 C100.2 C103.2 C104.2 C531.2 C532.2 C533.2 C584.2 C586.2 C587.2 C588.2 C589.2 C590.2 C595.2 C596.2 C597.2 C598.2 C614.2 C615.2 C616.2 C620.1 C1216.2 C1217.2 C1219.1 D1.K(CATHODE) D3.1(GND) J1.7 J2.5(GND) J2.6(CASE) J2.7(CASE) J2.8(CASE) J2.9(CASE) J3.13 J3.14 J10.11 J10.12 J48.A1(GND) J48.A4(GND) J48.A5(GND) J48.A8(GND) J48.A9(GND) J48.A12(GND) J48.A13(GND) J48.A16(GND) J48.A17(GND) J48.A20(GND) J48.A21(GND) J48.A24(GND) J48.A25(GND) J48.A28(GND) J48.A29(GND) J48.A32(GND) J48.A33(GND) J48.A36(GND) J48.A37(GND) J48.A40(GND) J48.B2(GND) J48.B3(GND) J48.B6(GND) J48.B7(GND) J48.B10(GND) J48.B11(GND) J48.B14(GND) J48.B15(GND) J48.B18(GND) J48.B19(GND) J48.B22(GND) J48.B23(GND) J48.B26(GND) J48.B27(GND) J48.B30(GND) J48.B31(GND) J48.B34(GND) J48.B35(GND) J48.B38(GND) J48.B39(GND) J48.C1(GND) J48.C4(GND) J48.C5(GND) J48.C8(GND) J48.C9(GND) J48.C12(GND) J48.C13(GND) J48.C16(GND) J48.C17(GND) J48.C20(GND) J48.C21(GND) J48.C24(GND) J48.C25(GND) J48.C28(GND) J48.C29(GND) J48.C32(GND) J48.C33(GND) J48.C36(GND) J48.C38(GND) J48.C40(GND) J48.D2(GND) J48.D3(GND) J48.D6(GND) J48.D7(GND) J48.D10(GND) J48.D13(GND) J48.D16(GND) J48.D19(GND) J48.D22(GND) J48.D25(GND) J48.D28(GND) J48.D37(GND) J48.D39(GND) J48.E1(GND) J48.E4(GND) J48.E5(GND) J48.E8(GND) J48.E11(GND) J48.E14(GND) J48.E17(GND) J48.E20(GND) J48.E23(GND) J48.E26(GND) J48.E29(GND) J48.E32(GND) J48.E35(GND) J48.E38(GND) J48.E40(GND) J48.F2(GND) J48.F3(GND) J48.F6(GND) J48.F9(GND) J48.F12(GND) J48.F15(GND) J48.F18(GND) J48.F21(GND) J48.F24(GND) J48.F27(GND) J48.F30(GND) J48.F33(GND) J48.F36(GND) J48.F39(GND) J48.G1(GND) J48.G4(GND) J48.G5(GND) J48.G8(GND) J48.G11(GND) J48.G14(GND) J48.G17(GND) J48.G20(GND) J48.G23(GND) J48.G26(GND) J48.G29(GND) J48.G32(GND) J48.G35(GND) J48.G38(GND) J48.G40(GND) J48.H3(GND) J48.H6(GND) J48.H9(GND) J48.H12(GND) J48.H15(GND) J48.H18(GND) J48.H21(GND) J48.H24(GND) J48.H27(GND) J48.H30(GND) J48.H33(GND) J48.H36(GND) J48.H39(GND) J48.J1(GND) J48.J4(GND) J48.J5(GND) J48.J8(GND) J48.J11(GND) J48.J14(GND) J48.J17(GND) J48.J20(GND) J48.J23(GND) J48.J26(GND) J48.J29(GND) J48.J32(GND) J48.J35(GND) J48.J38(GND) J48.J40(GND) J48.K2(GND) J48.K3(GND) J48.K6(GND) J48.K9(GND) J48.K12(GND) J48.K15(GND) J48.K18(GND) J48.K21(GND) J48.K24(GND) J48.K27(GND) J48.K30(GND) J48.K33(GND) J48.K36(GND) J48.K39(GND) JP3.2 JP15.1 JP17.2 Q1.E(EMITTER) Q29.E Q30.E Q31.E Q32.E Q33.E Q34.E R5.2 R15.1 R92.2 R95.1 R100.2 R180.2 R251.1 R252.1 R401.1 R625.2 R652.2 R653.2 R654.2 SW2.1(A1) SW2.3(A2) U1.1(GND) U1.5(GND) U1.10(AGND) U1.11(GND) U1.13(TEST) U1.15(GND) U1.25(GND) U1.35(GND) U1.47(GND) U1.51(GND) U2.5(VSS) U4.4(GND) U4.9(EPAD) U6.5(GND) U6.9(EPAD) U114.3(GND) U114.4(AGND) X1.2(G1) X1.4(G2) X3.2(GND) ; also on sheet 8 9 10 11 12 13 14 15 16 17 18 19 20
VBUS_5V00: C8.1 D3.6(VBUS) FB2.1 R1.2
VCC_1V80_FT: C11.1 C12.1 C13.1 C14.1 C15.1 U1.12(VCORE) U1.37(VCORE) U1.49(VREGOUT) U1.64(VCORE)
VCC_3V30: C1.1 C2.1 C3.1 C4.1 C5.1 C16.1 FB1.2 FB3.2 J1.1 J10.1 J10.2 R2.1 R3.1 R4.1 R11.2 R12.1 R13.1 R14.1 R16.2 R17.2 R83.2 R84.2 R85.2 R86.2 R87.2 R90.2 R91.2 R217.2 U1.20(VCCIO) U1.31(VCCIO) U1.42(VCCIO) U1.50(VREGIN) U1.56(VCCIO) U2.6(ORG) U2.8(VCC) ; also on sheet 8 10 11 13 14 16 17
VCC_12V00: C45.1 C46.1 C47.1 C97.1 C98.1 C99.1 C1216.1 J48.C35(12P0V) J48.C37(12P0V) R624.2 U6.1(EN) U6.8(VIN) U114.1(VIN) ; also on sheet 8 10 17
VCCIO0: C595.1 C596.1 C597.1 C598.1 U3.M12(VCCIO0) U3.V3(VCCIO0) U3.V7(VCCIO0) ; also on sheet 14
VCCIO1: C19.1 C20.1 C589.1 C590.1 U3.M7(VCCIO1) U3.N8(VCCIO1) U3.N11(VCCIO1) ; also on sheet 14
VCCIO1_IN: C23.2 C24.1 C25.1 FB6.1 J3.10 R38.1 R39.1 R40.1 R41.1 R56.2 R57.2 R58.2 R59.2 R60.2 R61.2 R109.2 U4.8(VCC) ; also on sheet 14
VCCIO2: C584.1 C586.1 C587.1 C588.1 U3.M10(VCCIO2) U3.R2(VCCIO2) U3.R4(VCCIO2) ; also on sheet 14
VCCIO2_IN: R22.1 R24.2 R25.2 R26.1 R27.1 R179.1 ; also on sheet 14
VCCIO3: C37.1 C38.1 C39.1 C40.1 C531.1 C616.1 R712.2 U3.AB3(VCCIO3) U3.AB6(VCCIO3) U3.AB9(VCCIO3) U3.AC11(VCCIO3) ; also on sheet 14
VCCIO4: C41.1 C42.1 C43.1 C44.1 C532.1 C615.1 R713.2 U3.AE8(VCCIO4) U3.AG4(VCCIO4) U3.AK3(VCCIO4) U3.AN2(VCCIO4) ; also on sheet 14
VCCIO5: C55.1 C56.1 C57.1 C58.1 C533.1 C614.1 R711.2 U3.AD14(VCCIO5) U3.AH12(VCCIO5) U3.AJ9(VCCIO5) U3.AL7(VCCIO5) ; also on sheet 14
12_MHz: JP6.2 JP65.3
125_DIS: JP15.2 R109.1 U3.L7(WRIO1_4A/MDQ4) X3.1(Standby)
125_MHz: R110.2 U3.N7(WRIO1_3B/PCLKRT1_0/MDS)
CFGMODE: SW7.2(COM_1) SW7.5(COM_2) U3.P1(CFGMODE)
CSSPIN: J3.8 JP51.1 U3.P7(WRIO1_3A/MCSN)
DM: D3.3(NC3) D3.4(D-) J2.2(D-) U1.7(DM)
DONE: DONE.1(TP) J3.4 R26.2 R28.2 U3.U4(DONE)
DP: D3.2(NC2) D3.5(D+) J2.3(D+) U1.8(DP)
DQ0_MOSI: J3.5 R46.1 U3.L12(WRIO1_0A/MDQ0)
DQ1_MISO: J3.7 R43.1 U3.L11(WRIO1_0B/MDQ1)
DQ2: J3.11 R45.2 U3.L10(WRIO1_2A/MDQ2)
DQ3: J3.9 R44.1 U3.L9(WRIO1_2B/MDQ3)
FLASH_CS: J3.2 JP51.2 R38.2 U4.1(CS#)
FMC1_CLK0_M2C_N: J48.H5(CLK0_M2C_N) U3.Y6(HPIO3_25B/PCLKRC3_3)
FMC1_CLK0_M2C_P: J48.H4(CLK0_M2C_P) U3.Y7(HPIO3_25A/PCLKRT3_3/DP0_DM8)
FMC1_CLK1_M2C_N: J48.G3(CLK1_M2C_N) U3.AE6(HPIO4_10B/PCLKC4_0/PCLKRC4_0/DP0_MA8)
FMC1_CLK1_M2C_P: J48.G2(CLK1_M2C_P) U3.AF6(HPIO4_10A/PCLKT4_0/PCLKRT4_0/DP0_DP0_MA7)
FMC1_CLK2_M2C_N: J48.K5(CLK2_M2C_N) U3.AJ6(HPIO5_25B/PCLKRC5_3/DP0_RAS_N)
FMC1_CLK2_M2C_P: J48.K4(CLK2_M2C_P) U3.AJ5(HPIO5_25A/PCLKRT5_3/DP0_BA0)
FMC1_CLK3_M2C_N: J48.J3(CLK3_M2C_N) U3.AE1(HPIO4_24B/PCLKRC4_2/DP0_ALERT_N)
FMC1_CLK3_M2C_P: J48.J2(CLK3_M2C_P) U3.AF1(HPIO4_24A/PCLKRT4_2/DP0_DM0)
FMC1_GA0: J48.C34(GA0) R249.1 R251.2
FMC1_GA1: J48.D35(GA1) R250.1 R252.2
FMC1_HA00_CLK_N: J48.F5(HA00_N_CC) U3.AJ11(HPIO5_10B/PCLKC5_0/PCLKRC5_0)
FMC1_HA00_CLK_P: J48.F4(HA00_P_CC) U3.AJ12(HPIO5_10A/PCLKT5_0/PCLKRT5_0/DP0_DM4)
FMC1_HA01_CLK_N: J48.E3(HA01_N_CC) U3.AE12(HPIO5_24B/PCLKRC5_2/DP0_CAS_N)
FMC1_HA01_CLK_P: J48.E2(HA01_P_CC) U3.AF12(HPIO5_24A/PCLKRT5_2/DP0_DM3)
FMC1_HA02_N: J48.K8(HA02_N) U3.AF14(HPIO5_6B/DP0_DQ39)
FMC1_HA02_P: J48.K7(HA02_P) U3.AE14(HPIO5_6A/DP0_DQ38)
FMC1_HA03_N: J48.J7(HA03_N) U3.AC14(HPIO5_4B/DP0_DQSN4)
FMC1_HA03_P: J48.J6(HA03_P) U3.AC15(HPIO5_4A/DP0_DQS4)
FMC1_HA04_N: J48.F8(HA04_N) U3.AA14(HPIO5_0B/DP0_DQ37)
FMC1_HA04_P: J48.F7(HA04_P) U3.AA15(HPIO5_0A/DP0_DQ36)
FMC1_HA05_N: J48.E7(HA05_N) U3.AB15(HPIO5_2B/DP0_DQ33)
FMC1_HA05_P: J48.E6(HA05_P) U3.AB14(HPIO5_2A/DP0_DQ32)
FMC1_HA06_N: J48.K11(HA06_N) U3.AJ7(HPIO5_21B/DP0_WE_N)
FMC1_HA06_P: J48.K10(HA06_P) U3.AK7(HPIO5_21A/DP0_MA14)
FMC1_HA07_N: J48.J10(HA07_N) U3.AJ10(HPIO5_16B/DP0_DQ25)
FMC1_HA07_P: J48.J9(HA07_P) U3.AH10(HPIO5_16A/DP0_DQ24)
FMC1_HA08_N: J48.F11(HA08_N) U3.AG11(HPIO5_20B/DP0_DQ31)
FMC1_HA08_P: J48.F10(HA08_P) U3.AG10(HPIO5_20A/DP0_DQ30)
FMC1_HA09_N: J48.E10(HA09_N) U3.AG13(HPIO5_8B/DP0_DQ35)
FMC1_HA09_P: J48.E9(HA09_P) U3.AG12(HPIO5_8A/DP0_DQ34)
FMC1_HA10_N: J48.K14(HA10_N) U3.AL9(HPIO5_3B/DP0_DQ17)
FMC1_HA10_P: J48.K13(HA10_P) U3.AL8(HPIO5_3A/DP0_DQ16)
FMC1_HA11_N: J48.J13(HA11_N) U3.AL6(HPIO5_19B/DP0_MA15)
FMC1_HA11_P: J48.J12(HA11_P) U3.AL5(HPIO5_19A/DP0_MA16)
FMC1_HA12_N: J48.F14(HA12_N) U3.AH8(HPIO5_22B/DP0_DQ27)
FMC1_HA12_P: J48.F13(HA12_P) U3.AH7(HPIO5_22A/DP0_DQ26)
FMC1_HA13_N: J48.E13(HA13_N) U3.AG9(HPIO5_18B/DP0_DQSN3)
FMC1_HA13_P: J48.E12(HA13_P) U3.AH9(HPIO5_18A/DP0_DQS3)
FMC1_HA14_N: J48.J16(HA14_N) U3.AP8(HPIO5_9B/DP0_DQ19)
FMC1_HA14_P: J48.J15(HA14_P) U3.AP9(HPIO5_9A/DP0_DQ18)
FMC1_HA15_N: J48.F17(HA15_N) U3.AK6(HPIO5_23B/DP0_BA1)
FMC1_HA15_P: J48.F16(HA15_P) U3.AK5(HPIO5_23A/DP0_BA2)
FMC1_HA16_N: J48.E16(HA16_N) U3.AK11(HPIO5_14B/DP0_DQ29)
FMC1_HA16_P: J48.E15(HA16_P) U3.AK10(HPIO5_14A/DP0_DQ28)
FMC1_HA17_CLK_N: J48.K17(HA17_N_CC) U3.AP7(HPIO5_11B/PCLKC5_1/PCLKRC5_1)
FMC1_HA17_CLK_P: J48.K16(HA17_P_CC) U3.AN7(HPIO5_11A/PCLKT5_1/PCLKRT5_1/DP0_DM2)
FMC1_HA18_N: J48.J19(HA18_N) U3.AM9(HPIO5_5B/DP0_DQSN2)
FMC1_HA18_P: J48.J18(HA18_P) U3.AM8(HPIO5_5A/DP0_DQS2)
FMC1_HA19_N: J48.F20(HA19_N) U3.AK8(HPIO5_1B/DP0_DQ21)
FMC1_HA19_P: J48.F19(HA19_P) U3.AK9(HPIO5_1A/DP0_DQ20)
FMC1_HA20_N: J48.E19(HA20_N) U3.AM5(HPIO5_17B/DP0_MCLKC2)
FMC1_HA20_P: J48.E18(HA20_P) U3.AM6(HPIO5_17A/DP0_MCLKT2)
FMC1_HA21_N: J48.K20(HA21_N) U3.AN5(HPIO5_15B/DP0_MCLKC3)
FMC1_HA21_P: J48.K19(HA21_P) U3.AN6(HPIO5_15A/DP0_MCLKT3)
FMC1_HA22_N: J48.J22(HA22_N) U3.AP6(HPIO5_13B/PLLC5_IN)
FMC1_HA22_P: J48.J21(HA22_P) U3.AP5(HPIO5_13A/PLLT5_IN)
FMC1_HA23_N: J48.K23(HA23_N) U3.AN8(HPIO5_7B/DP0_DQ23)
FMC1_HA23_P: J48.K22(HA23_P) U3.AN9(HPIO5_7A/DP0_DQ22)
FMC1_HB00_N_CC: J48.K26(HB00_N_CC) U3.AC1(HPIO3_11B/PCLKC3_1/PCLKRC3_1)
FMC1_HB00_P_CC: J48.K25(HB00_P_CC) U3.AB1(HPIO3_11A/PCLKT3_1/PCLKRT3_1/DP0_DM6)
FMC1_HB01_N: J48.J25(HB01_N) U3.AD10(HPIO3_6B/DP0_DQ40)
FMC1_HB01_P: J48.J24(HB01_P) U3.AD9(HPIO3_6A/DP0_DQ41)
FMC1_HB02_N: J48.F23(HB02_N) U3.AD5(HPIO3_1B/DP0_DQ50)
FMC1_HB02_P: J48.F22(HB02_P) U3.AD6(HPIO3_1A/DP0_DQ51)
FMC1_HB03_N: J48.E22(HB03_N) U3.AC5(HPIO3_5B/DP0_DQSN6)
FMC1_HB03_P: J48.E21(HB03_P) U3.AC4(HPIO3_5A/DP0_DQS6)
FMC1_HB04_N: J48.F26(HB04_N) U3.AC10(HPIO3_20B/DP0_DQ56)
FMC1_HB04_P: J48.F25(HB04_P) U3.AB10(HPIO3_20A/DP0_DQ57)
FMC1_HB05_N: J48.E25(HB05_N) U3.AD8(HPIO3_8B/DP0_DQ44)
FMC1_HB05_P: J48.E24(HB05_P) U3.AD7(HPIO3_8A/DP0_DQ45)
FMC1_HB06_N_CC: J48.K29(HB06_N_CC) U3.AM2(HPIO4_13B/PLLC4_IN/DP0_PLLC4_IN)
FMC1_HB06_P_CC: J48.K28(HB06_P_CC) U3.AL2(HPIO4_13A/PLLT4_IN/DP0_PLLT4_IN)
FMC1_HB07_N: J48.J28(HB07_N) U3.AD11(HPIO3_4B/DP0_DQSN5)
FMC1_HB07_P: J48.J27(HB07_P) U3.AD12(HPIO3_4A/DP0_DQS5)
FMC1_HB08_N: J48.F29(HB08_N) U3.AF7(HPIO4_8B/DP0_MA6)
FMC1_HB08_P: J48.F28(HB08_P) U3.AE7(HPIO4_8A/DP0_MA5)
FMC1_HB09_N: J48.E28(HB09_N) U3.AF5(HPIO4_14B/DP0_DQ02)
FMC1_HB09_P: J48.E27(HB09_P) U3.AE5(HPIO4_14A/DP0_DQ03)
FMC1_HB10_N: J48.K32(HB10_N) U3.AN3(HPIO4_9B/DP0_MA11)
FMC1_HB10_P: J48.K31(HB10_P) U3.AM3(HPIO4_9A/DP0_MA10)
FMC1_HB11_N: J48.J31(HB11_N) U3.AK4(HPIO4_3B/DP0_ODT1)
FMC1_HB11_P: J48.J30(HB11_P) U3.AJ4(HPIO4_3A/DP0_CKE1)
FMC1_HB12_N: J48.F32(HB12_N) U3.AH3(HPIO4_21B/DP0_DQ08)
FMC1_HB12_P: J48.F31(HB12_P) U3.AH4(HPIO4_21A/DP0_DQ09)
FMC1_LA00_CLK_N: J48.G7(LA00_N_CC) U3.AA7(HPIO3_24B/PCLKRC3_2)
FMC1_LA00_CLK_P: J48.G6(LA00_P_CC) U3.AB7(HPIO3_24A/PCLKRT3_2/DP0_DM7)
FMC1_LA01_CLK_N: J48.D9(LA01_N_CC) U3.AC9(HPIO3_10B/PCLKC3_0/PCLKRC3_0)
FMC1_LA01_CLK_P: J48.D8(LA01_P_CC) U3.AC8(HPIO3_10A/PCLKT3_0/PCLKRT3_0/DP0_DM5)
FMC1_LA02_N: J48.H8(LA02_N) U3.AB12(HPIO3_0B/DP0_DQ42)
FMC1_LA02_P: J48.H7(LA02_P) U3.AB13(HPIO3_0A/DP0_DQ43)
FMC1_LA03_N: J48.G10(LA03_N) U3.Y10(HPIO3_14B/DP0_DQ58)
FMC1_LA03_P: J48.G9(LA03_P) U3.Y11(HPIO3_14A/DP0_DQ59)
FMC1_LA04_N: J48.H11(LA04_N) U3.AC12(HPIO3_2B/DP0_DQ46)
FMC1_LA04_P: J48.H10(LA04_P) U3.AC13(HPIO3_2A/DP0_DQ47)
FMC1_LA05_N: J48.D12(LA05_N) U3.AA9(HPIO3_22B/DP0_DQ60)
FMC1_LA05_P: J48.D11(LA05_P) U3.AA8(HPIO3_22A/DP0_DQ61)
FMC1_LA06_N: J48.C11(LA06_N) U3.Y9(HPIO3_16B/DP0_DQ62)
FMC1_LA06_P: J48.C10(LA06_P) U3.Y8(HPIO3_16A/DP0_DQ63)
FMC1_LA07_N: J48.H14(LA07_N) U3.AA1(HPIO3_13B/PLLC3_IN)
FMC1_LA07_P: J48.H13(LA07_P) U3.Y1(HPIO3_13A/PLLT3_IN)
FMC1_LA08_N: J48.G13(LA08_N) U3.AB5(HPIO3_19B/DP0_DQSN8)
FMC1_LA08_P: J48.G12(LA08_P) U3.AB4(HPIO3_19A/DP0_DQS8)
FMC1_LA09_N: J48.D15(LA09_N) U3.Y2(HPIO3_15B/DP0_DQ66)
FMC1_LA09_P: J48.D14(LA09_P) U3.AA2(HPIO3_15A/DP0_DQ67)
FMC1_LA10_N: J48.C15(LA10_N) U3.AA5(HPIO3_23B/DP0_DQ68)
FMC1_LA10_P: J48.C14(LA10_P) U3.Y5(HPIO3_23A/DP0_DQ69)
FMC1_LA11_N: J48.H17(LA11_N) U3.AD4(HPIO3_3B/DP0_DQ54)
FMC1_LA11_P: J48.H16(LA11_P) U3.AD3(HPIO3_3A/DP0_DQ55)
FMC1_LA12_N: J48.G16(LA12_N) U3.Y3(HPIO3_17B/DP0_DQ70)
FMC1_LA12_P: J48.G15(LA12_P) U3.AA3(HPIO3_17A/DP0_DQ71)
FMC1_LA13_N: J48.D18(LA13_N) U3.Y4(HPIO3_21B/DP0_DQ64)
FMC1_LA13_P: J48.D17(LA13_P) U3.AA4(HPIO3_21A/DP0_DQ65)
FMC1_LA14_N: J48.C19(LA14_N) U3.AC2(HPIO3_7B/DP0_DQ48)
FMC1_LA14_P: J48.C18(LA14_P) U3.AC3(HPIO3_7A/DP0_DQ49)
FMC1_LA15_N: J48.H20(LA15_N) U3.AC6(HPIO3_18B/DP0_DQSN7)
FMC1_LA15_P: J48.H19(LA15_P) U3.AC7(HPIO3_18A/DP0_DQS7)
FMC1_LA16_N: J48.G19(LA16_N) U3.AD1(HPIO3_9B/DP0_DQ52)
FMC1_LA16_P: J48.G18(LA16_P) U3.AD2(HPIO3_9A/DP0_DQ53)
FMC1_LA17_CLK_N: J48.D21(LA17_N_CC) U3.AP3(HPIO4_11B/PCLKC4_1/PCLKRC4_1/DP0_MA13)
FMC1_LA17_CLK_P: J48.D20(LA17_P_CC) U3.AP2(HPIO4_11A/PCLKT4_1/PCLKRT4_1/DP0_MA12)
FMC1_LA18_CLK_N: J48.C23(LA18_N_CC) U3.AJ1(HPIO4_25B/PCLKRC4_3/DP0_RST_N)
FMC1_LA18_CLK_P: J48.C22(LA18_P_CC) U3.AH1(HPIO4_25A/PCLKRT4_3/DP0_DM1)
FMC1_LA19_N: J48.H23(LA19_N) U3.AF4(HPIO4_16B/DP0_DQ06)
FMC1_LA19_P: J48.H22(LA19_P) U3.AE4(HPIO4_16A/DP0_DQ07)
FMC1_LA20_N: J48.G22(LA20_N) U3.AF2(HPIO4_20B/DP0_DQ00)
FMC1_LA20_P: J48.G21(LA20_P) U3.AE2(HPIO4_20A/DP0_DQ01)
FMC1_LA21_N: J48.H26(LA21_N) U3.AK2(HPIO4_19B/DP0_DQSN1)
FMC1_LA21_P: J48.H25(LA21_P) U3.AJ2(HPIO4_19A/DP0_DQS1)
FMC1_LA22_N: J48.G25(LA22_N) U3.AG2(HPIO4_22B/DP0_DQ04)
FMC1_LA22_P: J48.G24(LA22_P) U3.AG1(HPIO4_22A/DP0_DQ05)
FMC1_LA23_N: J48.D24(LA23_N) U3.AE3(HPIO4_18B/DP0_DQSN0)
FMC1_LA23_P: J48.D23(LA23_P) U3.AF3(HPIO4_18A/DP0_DQS0)
FMC1_LA24_N: J48.H29(LA24_N) U3.AJ3(HPIO4_23B/DP0_DQ12)
FMC1_LA24_P: J48.H28(LA24_P) U3.AH2(HPIO4_23A/DP0_DQ13)
FMC1_LA25_N: J48.G28(LA25_N) U3.AK1(HPIO4_17B/DP0_DQ14)
FMC1_LA25_P: J48.G27(LA25_P) U3.AL1(HPIO4_17A/DP0_DQ15)
FMC1_LA26_N: J48.D27(LA26_N) U3.AF11(HPIO4_0B/DP0_MCLKC0)
FMC1_LA26_P: J48.D26(LA26_P) U3.AE11(HPIO4_0A/DP0_MCLKT0)
FMC1_LA27_N: J48.C27(LA27_N) U3.AE10(HPIO4_2B/DP0_MA0)
FMC1_LA27_P: J48.C26(LA27_P) U3.AF10(HPIO4_2A/DP0_CKE0)
FMC1_LA28_N: J48.H32(LA28_N) U3.AH5(HPIO4_1B/DP0_MCLKC1)
FMC1_LA28_P: J48.H31(LA28_P) U3.AH6(HPIO4_1A/DP0_MCLKT1)
FMC1_LA29_N: J48.G31(LA29_N) U3.AG8(HPIO4_6B/DP0_MA4)
FMC1_LA29_P: J48.G30(LA29_P) U3.AG7(HPIO4_6A/DP0_MA3)
FMC1_LA30_N: J48.H35(LA30_N) U3.AM1(HPIO4_15B/DP0_DQ10)
FMC1_LA30_P: J48.H34(LA30_P) U3.AN1(HPIO4_15A/DP0_DQ11)
FMC1_LA31_N: J48.G34(LA31_N) U3.AE9(HPIO4_4B/DP0_MA2)
FMC1_LA31_P: J48.G33(LA31_P) U3.AF9(HPIO4_4A/DP0_MA1)
FMC1_LA32_N: J48.H38(LA32_N) U3.AP4(HPIO4_7B/DP0_MA9)
FMC1_LA32_P: J48.H37(LA32_P) U3.AN4(HPIO4_7A/DP0_CS_N0)
FMC1_LA33_N: J48.G37(LA33_N) U3.AL4(HPIO4_5B/DP0_CS_N1)
FMC1_LA33_P: J48.G36(LA33_P) U3.AM4(HPIO4_5A/DP0_ODT0)
FMC1_PG_C2M: J10.4 J48.D1(PG_C2M) R83.1 U3.V4(WRIO0_2A)
FMC1_PG_M2C: J10.5 J48.F1(PG_M2C) R84.1 U3.W4(WRIO0_2B)
FMC1_PRSNT_M2C_L: J10.8 J48.H2(PRSNT_M2C_L) R217.1 U3.U7(WRIO0_3A)
FMC1_RES0: R216.2 U3.W5(WRIO0_0A)
FMC1_RES1: R215.2 U3.V5(WRIO0_0B)
FMC1_SCL: J10.10 J48.C30(SCL) R90.1 U3.T8(WRIO0_1B/PCLKT0_1/PCLKRT0_1)
FMC1_SDA: J10.14 J48.C31(SDA) R91.1 U3.U8(WRIO0_1A)
FMC1_TCK: J10.3 J48.D29(TCK) R55.1 R92.1
FMC1_TDI: J10.7 J48.D30(TDI) R85.1 U3.W1(WRIO0_4A)
FMC1_TDO: J10.9 J48.D31(TDO) R86.1 U3.V1(WRIO0_4B)
FMC1_TMS: J10.13 J48.D33(TMS) R87.1 U3.W7(WRIO0_5A)
FMC1_TRST_L: J10.6 J48.D34(TRST_L)
FMC1_VREFA: J48.H1(VREF_A_M2C) JP38.2 JP88.3 JP89.3
FMC1_VREFB: J48.K1(VREF_B_M2C) JP88.1 JP89.1
INITN: D4.K(CATHODE) INIT.1(TP) J3.6 R22.2 U3.T5(INITN)
LED_0: R687.2 U3.L8(WRIO1_4B/MDQ5)
LED_1: R688.2 U3.P8(WRIO1_5B/MCLKN)
LED_2: R689.2 U3.M8(WRIO1_6A/MDQ6)
LED_3: R690.2 U3.M9(WRIO1_6B/MDQ7)
LED_4: R691.2 U3.P10(WRIO1_7A)
LED_5: R692.2 U3.N10(WRIO1_7B)
PROGRAMN: C22.1 J3.1 JP17.1 PROGRAMN.1(TP) R10.2 R27.2 R29.1 R408.1 U3.P2(PROGRAMN)
RASP_IO04: U3.P6(WRIO2_2A/SDQ2) ; also on sheet 13
RASP_IO07: JP65.1 ; also on sheet 13
RASP_IO08: U3.P5(WRIO2_2B/SDQ3) ; also on sheet 13
RASP_IO09: U3.R5(WRIO2_3B/SDS) ; also on sheet 13
RASP_IO10: U3.R6(WRIO2_3A/SCSN) ; also on sheet 13
RASP_IO12: U3.U5(WRIO2_1B/SSDO) ; also on sheet 13
RASP_IO16: U3.N6(WRIO2_0A/SDQ0) ; also on sheet 13
RASP_IO20: U3.T6(WRIO0_7B/PLLTFB0_IN) ; also on sheet 13
RASP_IO21: U3.U6(WRIO0_7A/PLLT0_IN) ; also on sheet 13
RASP_IO22: U3.W6(WRIO0_5B) ; also on sheet 13
RASP_IO23: U3.P4(WRIO2_4B/SDQ5) ; also on sheet 13
RASP_IO24: U3.N5(WRIO2_0B/SDQ1) ; also on sheet 13
RASP_IO25: U3.V2(WRIO0_6A) ; also on sheet 13
RASP_IO27: U3.P3(WRIO2_4A/SDQ4) ; also on sheet 13
RXD_UART: JP2.2 U3.R3(WRIO2_6A/SDQ6)
SCL: JP4.2 ; also on sheet 13
SDA: JP5.2 ; also on sheet 13
SPI_MCLK: J3.12 R20.1 R40.2 U4.6(SCLK)
TCK: J1.8 R5.1 R6.2 U3.T1(TCK) ; also on sheet 13
TDI: J1.3 R3.2 R7.2 U3.U1(TDI) ; also on sheet 13
TDO: J1.2 R4.2 R8.2 U3.U2(TDO) ; also on sheet 13
TMS: J1.6 R2.2 R9.2 U3.R1(TMS) ; also on sheet 13
TXD_UART: JP1.2 U3.T3(WRIO2_6B/SDQ7)
VFMC1_3V30: C49.1 C50.1 C51.1 C52.1 FB4.2 J48.C39(3P3V) J48.D36(3P3V) J48.D38(3P3V) J48.D40(3P3V) L1.2 R95.2 R96.1 VFMC1_3V30.1 ; also on sheet 8
VFMC1_3V30AUX: C620.2 FB4.1 J48.D32(3P3VAUX) R249.2 R250.2 ; also on sheet 8
VFMC1_ADJ: C100.1 C101.1 C103.1 C104.1 C1217.1 J48.E39(VADJ) J48.F40(VADJ) J48.G39(VADJ) J48.H40(VADJ) L13.2 R399.2 VFMC1_ADJ.1(TP) ; also on sheet 8 14
N00911: C6.1 C7.1 FB1.1 U1.9(VPLL)
N00925: C9.1 C10.1 FB3.1 U1.4(VPHY)
N01606: JP3.1 R11.1 U1.14(RESET#)
N01656: R15.2 U1.6(REF)
N02092: R12.2 U1.63(EECS) U2.1(CS)
N02098: R13.2 U1.62(EECLK) U2.2(CLK)
N02124: R19.1 U1.61(EEDATA) U2.3(DI)
N02138: R14.2 R19.2 U2.4(DO)
N02805: C17.2 U1.2(OSCI) X1.1
N02831: C18.2 JP6.1 U1.3(OSCO) X1.3
N03813: R9.1 U1.19(ADBUS3)
N03929: R7.1 U1.17(ADBUS1)
N03953: R8.1 U1.18(ADBUS2)
N16504386: FB2.2 J2.1(VCC)
N16632009: JP2.1 JP5.1 R16.1 U1.39(BDBUS1) U1.40(BDBUS2)
N16632070: JP1.1 JP4.1 R17.1 U1.38(BDBUS0)
N16986163: R39.2 R45.1 U4.3(WP#/SIO2)
N16986174: R41.2 R44.2 U4.7(RESET#/SIO3)
N16986210: R43.2 U4.2(SO/SIO1)
N17591276: R10.1 U1.24(ADBUS7)
N17596855: R6.1 U1.16(ADBUS0)
N18595602: D1.A(ANODE) R1.1
N20181793: C52.2 R96.2 R100.1 U6.2(FB)
N20181835: C48.1 U6.7(BOOT)
N20181965: C54.1 U6.4(SS)
N20181967: C53.1 U6.3(VREG)
N20182036: C48.2 L1.1 U6.6(SW)
N20325017: J48.B1(RES1) R215.1
N20325029: J48.B40(RES0) R216.1
N20421551: JP88.2 U3.AA11(HPIO3_12A/VREF3/DP0_VREF3)
N20986575: D4.A(ANODE) R24.1
N20986579: D5.K(CATHODE) Q1.C(COLLECTOR)
N20986602: D5.A(ANODE) R25.1
N20986712: Q1.B(BASE) R28.1
N20987029: R29.2 SW2.2(B1) SW2.4(B2)
N21000300: R46.2 U4.5(SI/SIO0)
N21001542: R20.2 U3.P9(WRIO1_5A/MCLK)
N21002825: JP65.2 U3.U3(WRIO2_5A/PCLKRT2_0/SCLKP)
N21037031: R55.2 U3.T7(WRIO0_3B/PCLKT0_0/PCLKRT0_0)
N21077063: D9.K(CATHODE) Q32.C
N21077065: D11.K(CATHODE) Q34.C
N21077067: D10.K(CATHODE) Q33.C
N21077110: D6.K(CATHODE) Q29.C
N21077112: D7.K(CATHODE) Q30.C
N21077121: D8.K(CATHODE) Q31.C
N21077214: D10.A(ANODE) R60.1
N21077216: D7.A(ANODE) R57.1
N21077218: D6.A(ANODE) R56.1
N21077222: D11.A(ANODE) R61.1
N21077224: D8.A(ANODE) R58.1
N21077226: D9.A(ANODE) R59.1
N21167890: R408.2 U3.R8(WRIO1_1B/MSDO)
N21221554: R652.1 R712.1 U3.AA10(EXT_RES3/DP0_EXT_RES3)
N21892437: R180.1 SW7.3(NC_1) SW7.6(NC_2)
N21892555: R179.2 SW7.1(NO) SW7.4(NO_2)
N22461237: R654.1 R711.1 U3.AE13(EXT_RES5/DP0_EXT_RES5)
N22461561: JP38.1 U3.AF13(HPIO5_12A/VREF5/DP0_VREF5)
N22463394: JP89.2 U3.AG6(HPIO4_12A/VREF4/DP0_VREF4)
N22463398: R653.1 R713.1 U3.AG5(EXT_RES4/DP0_EXT_RES4)
N22530625: C1219.2 R624.1 R625.1 U114.5(EN)
N22531796: C101.2 R399.1 R401.2 U114.6(FB)
N22531852: L13.1 U114.2(SW)
N22778746: J48.K40(VIO_B_M2C-2) TP_M2C_B_1_2.1(TP)
N22778748: J48.J39(VIO_B_M2C-1) TP_M2C_B_1_1.1(TP)
N23029118: C69.1 FB6.2 X3.4(VDD)
N23029151: R110.1 X3.3(OUT)
N23067021: Q29.B R687.1
N23067044: Q30.B R688.1
N23067876: Q31.B R689.1
N23067899: Q32.B R690.1
N23068194: Q33.B R691.1
N23068217: Q34.B R692.1

Not connected (* = marked no-connect by the designer): J1 4* 5*; J2 4(NC)* 10(MH1)* 11(MH2)*; J3 3*; J48 A2(DP1_M2C_P)* A3(DP1_M2C_N)* A6(DP2_M2C_P)* A7(DP2_M2C_N)* A10(DP3_M2C_P)* A11(DP3_M2C_N)* A14(DP4_M2C_P)* A15(DP4_M2C_N)* A18(DP5_M2C_P)* A19(DP5_M2C_N)* A22(DP1_C2M_P)* A23(DP1_C2M_N)* A26(DP2_C2M_P)* A27(DP2_C2M_N)* A30(DP3_C2M_P)* A31(DP3_C2M_N)* A34(DP4_C2M_P)* A35(DP4_C2M_N)* A38(DP5_C2M_P)* A39(DP5_C2M_N)* B4(DP9_M2C_P)* B5(DP9_M2C_N)* B8(DP8_M2C_P)* B9(DP8_M2C_N)* B12(DP7_M2C_P)* B13(DP7_M2C_N)* B16(DP6_M2C_P)* B17(DP6_M2C_N)* B20(GBTCLK1_M2C_P)* B21(GBTCLK1_M2C_N)* B24(DP9_C2M_P)* B25(DP9_C2M_N)* B28(DP8_C2M_P)* B29(DP8_C2M_N)* B32(DP7_C2M_P)* B33(DP7_C2M_N)* B36(DP6_C2M_P)* B37(DP6_C2M_N)* C2(DP0_C2M_P)* C3(DP0_C2M_N)* C6(DP0_M2C_P)* C7(DP0_M2C_N)* D4(GBTCLK0_M2C_P)* D5(GBTCLK0_M2C_N)* E30(HB13_P)* E31(HB13_N)* E33(HB19_P)* E34(HB19_N)* E36(HB21_P)* E37(HB21_N)* F34(HB16_P)* F35(HB16_N)* F37(HB20_P)* F38(HB20_N)* J33(HB15_P)* J34(HB15_N)* J36(HB18_P)* J37(HB18_N)* K34(HB14_~{P})* K35(HB14_N)* K37(HB17_P_CC)* K38(HB17_N_CC)*; U1 21(ADBUS4)* 22(ADBUS5)* 23(ADBUS6)* 26(ACBUS0)* 27(ACBUS1)* 28(ACBUS2)* 29(ACBUS3)* 30(ACBUS4)* 32(ACBUS5)* 33(ACBUS6)* 34(ACBUS7)* 36(SUSPEND#)* 41(BDBUS3)* 43(BDBUS4)* 44(BDBUS5)* 45(BDBUS6)* 46(BDBUS7)* 48(BCBUS0)* 52(BCBUS1)* 53(BCBUS2)* 54(BCBUS3)* 55(BCBUS4)* 57(BCBUS5)* 58(BCBUS6)* 59(BCBUS7)* 60(PWREN#)*; U2 7(NU)*

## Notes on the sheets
sheet 1
- Avant-E70 Development Board REVA
- 01 - Title Page
  02 - Block Diagram
  03 - USB Interface
  04 - Bank-0,1 External Flash
  05 - Bank-2 JTAG, UART
  06 - Bank-3,4,5 FMC1
  07 - FMC1 LA&HA
  08 - Bank-6 LED,SWITCH
  09 - Bank-7,8 FMC2
  10 - FMC2 LA
  11 - Bank-9,10,11 LPDDR4
  12 - Bank-12,13 PMODs
  13 - Bank-14 Segment & RPi
  14 - Bank Power
  15 - Power Decoupling
  16 - Power Supplies 1
  17 - Power Supplies 2
  18 - Ground
  19 - Platform Manager 2
  20 - USB Power Sink
  21 - Power Block Diagram
sheet 3
- Route USB pair 90 ohm impedance
- TXD_UART
- RXD_UART
- FTDI_RST
- FTDI_SCL
- Default = OPEN
- FTDI_SDA
- DEFAULT SETTINGS:
  JP1 = OPEN
  JP2 = OPEN
  JP4 = OPEN
  JP5 = OPEN
- 12_MHz
- Default = OPEN
sheet 4
- LEDs
- LEDs Signal Map
- U3 pin
- Signal
- LED
- L8
- LED_0
- D6
- P8
- LED_1
- D7
- M8
- LED_2
- D8
- M9
- LED_3
- D9
- BANK 0
  3.3V
- P10
- LED_4
- D10
- N10
- LED_5
- D11
- X3_DIS
- Default = OPEN
- 50 ohm trace
- BANK 1
  3.3V
- 2.5 x 2.0 mm 4-SMD
- Place X3 close to U3
- Parallel / SPI Config Header
- Default = CLOSED
- Place close to Flash
- 512 Mb SPI Flash
sheet 5
- INITN indicator will light
  if an error occurs during
  configuration programming
- Default = OPEN
- INITN
- BANK 2
  3.3V
- DONE indicator will light when
  configuration is successfully
  completed
- MSPI
- DONE
- JTAG
- PROGRAMN
sheet 6
- Default = OPEN
- Default = OPEN
- BANK 3
  1.8V
- BANK 4
  1.8V
- FMC1 Supported:
  LA[0:33]
  HA[0:23]
  HB[0:12]
- Default = OPEN
- BANK 5
  1.8V
sheet 7
- Default:1.8V@4A
- Vout=0.6*(1+R339/R401)=1.8V
- Parallel FMC CFG Header
